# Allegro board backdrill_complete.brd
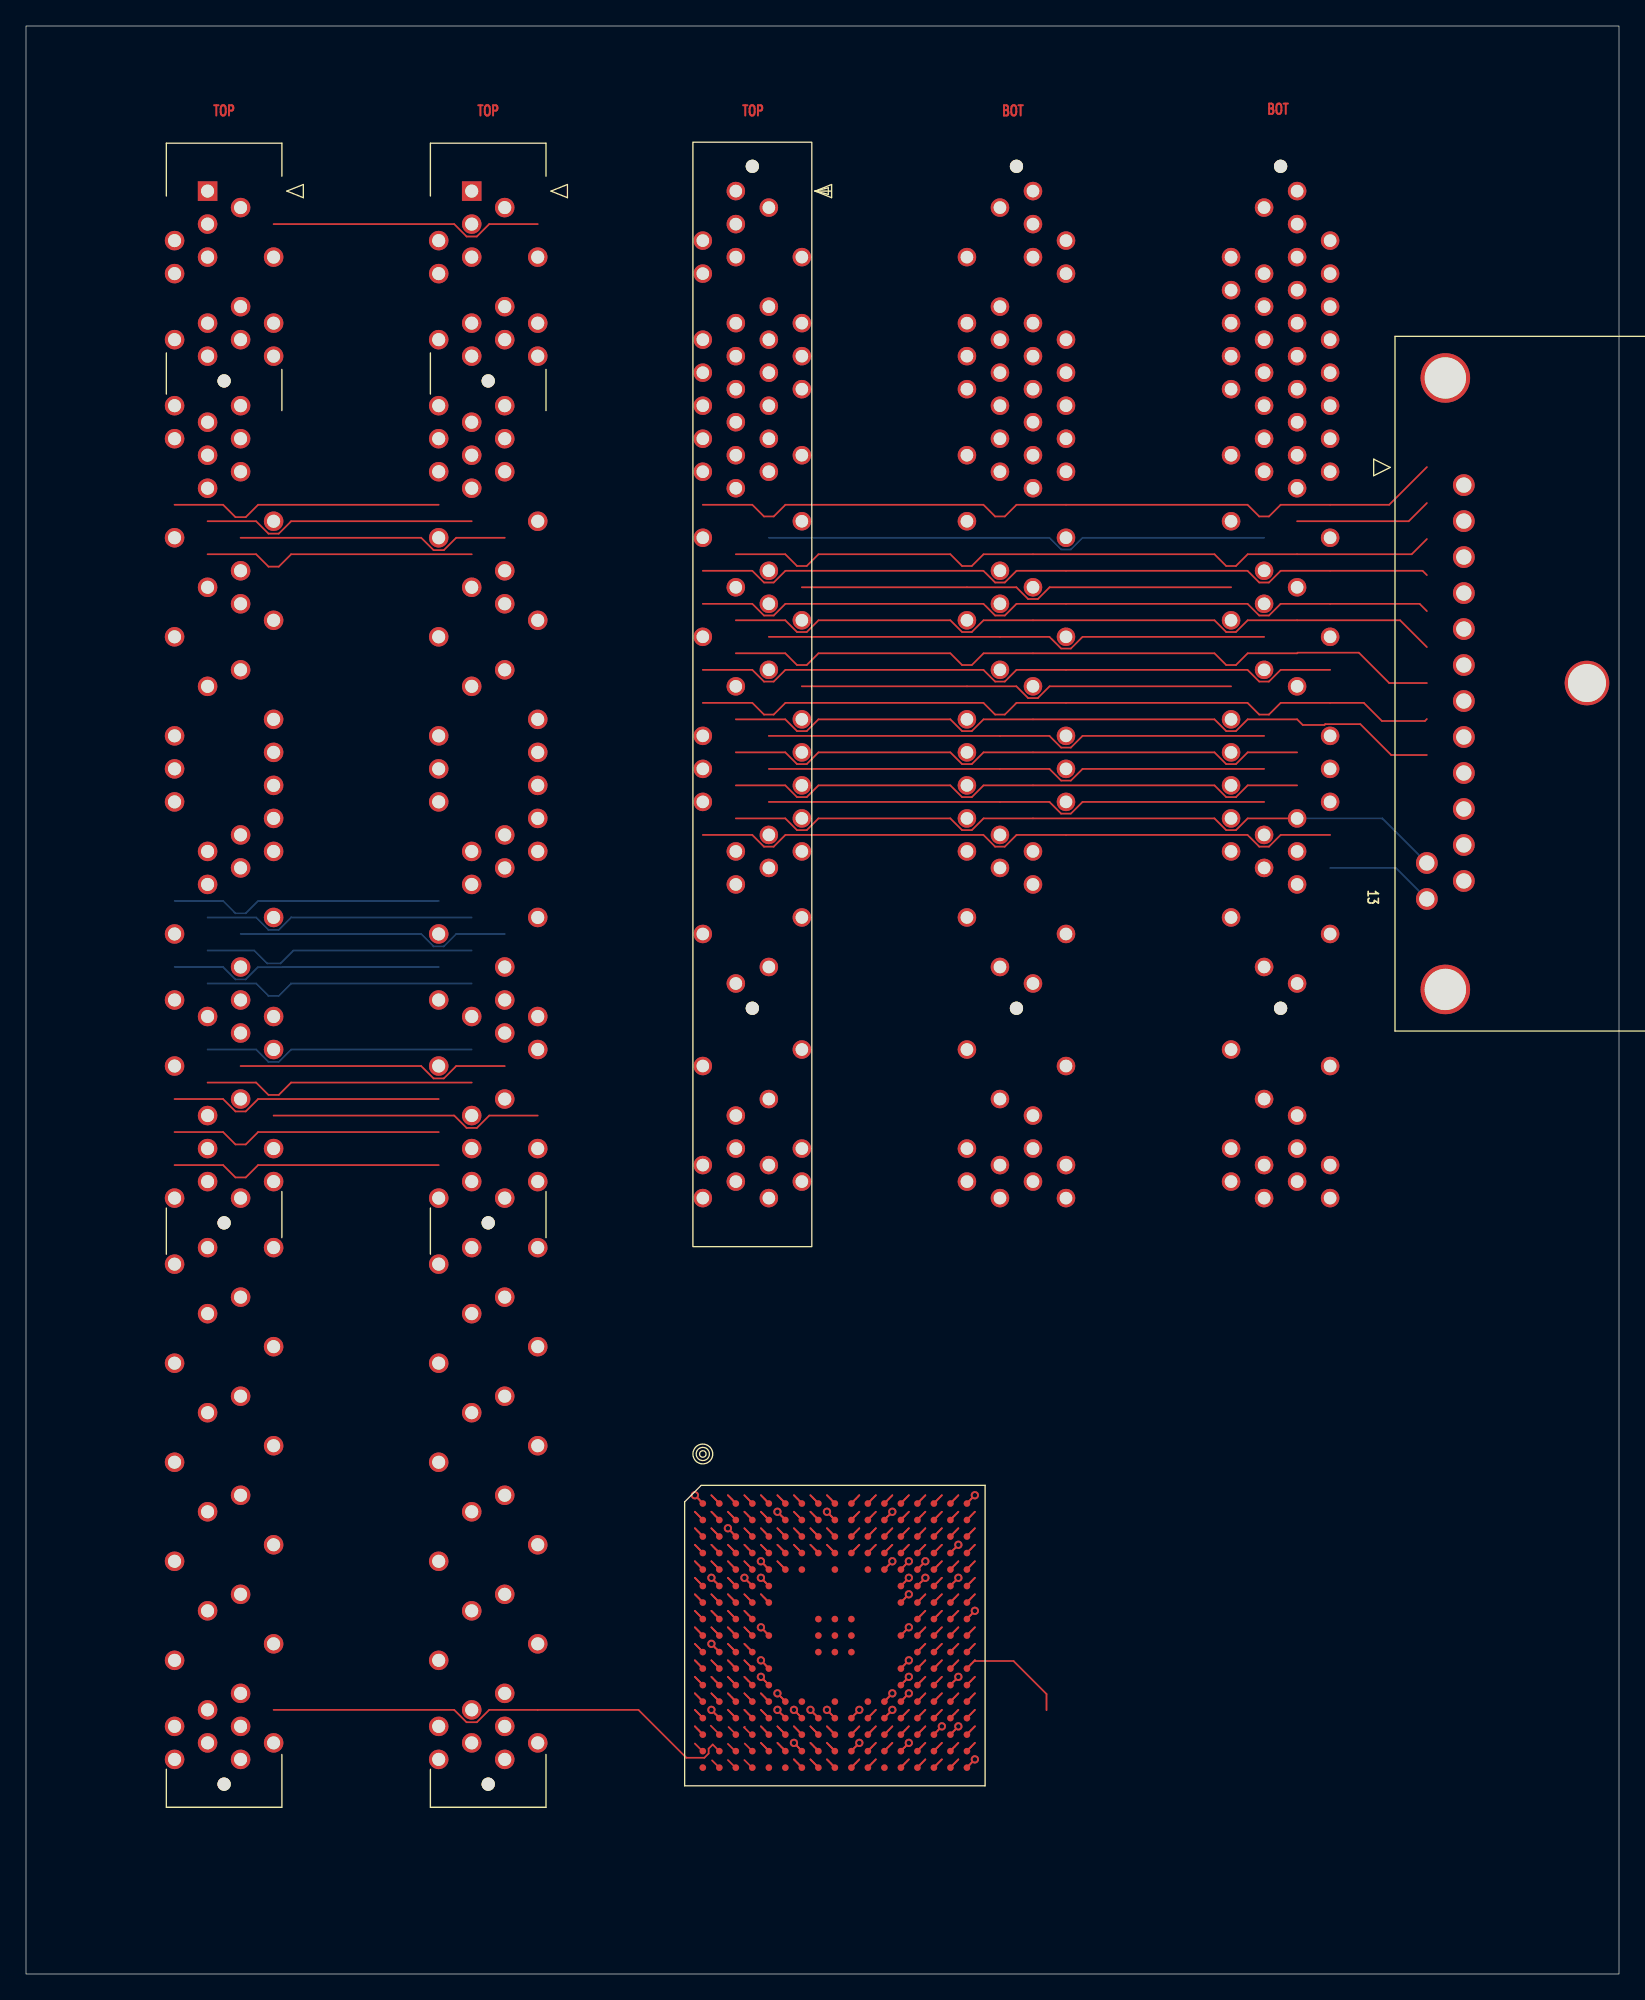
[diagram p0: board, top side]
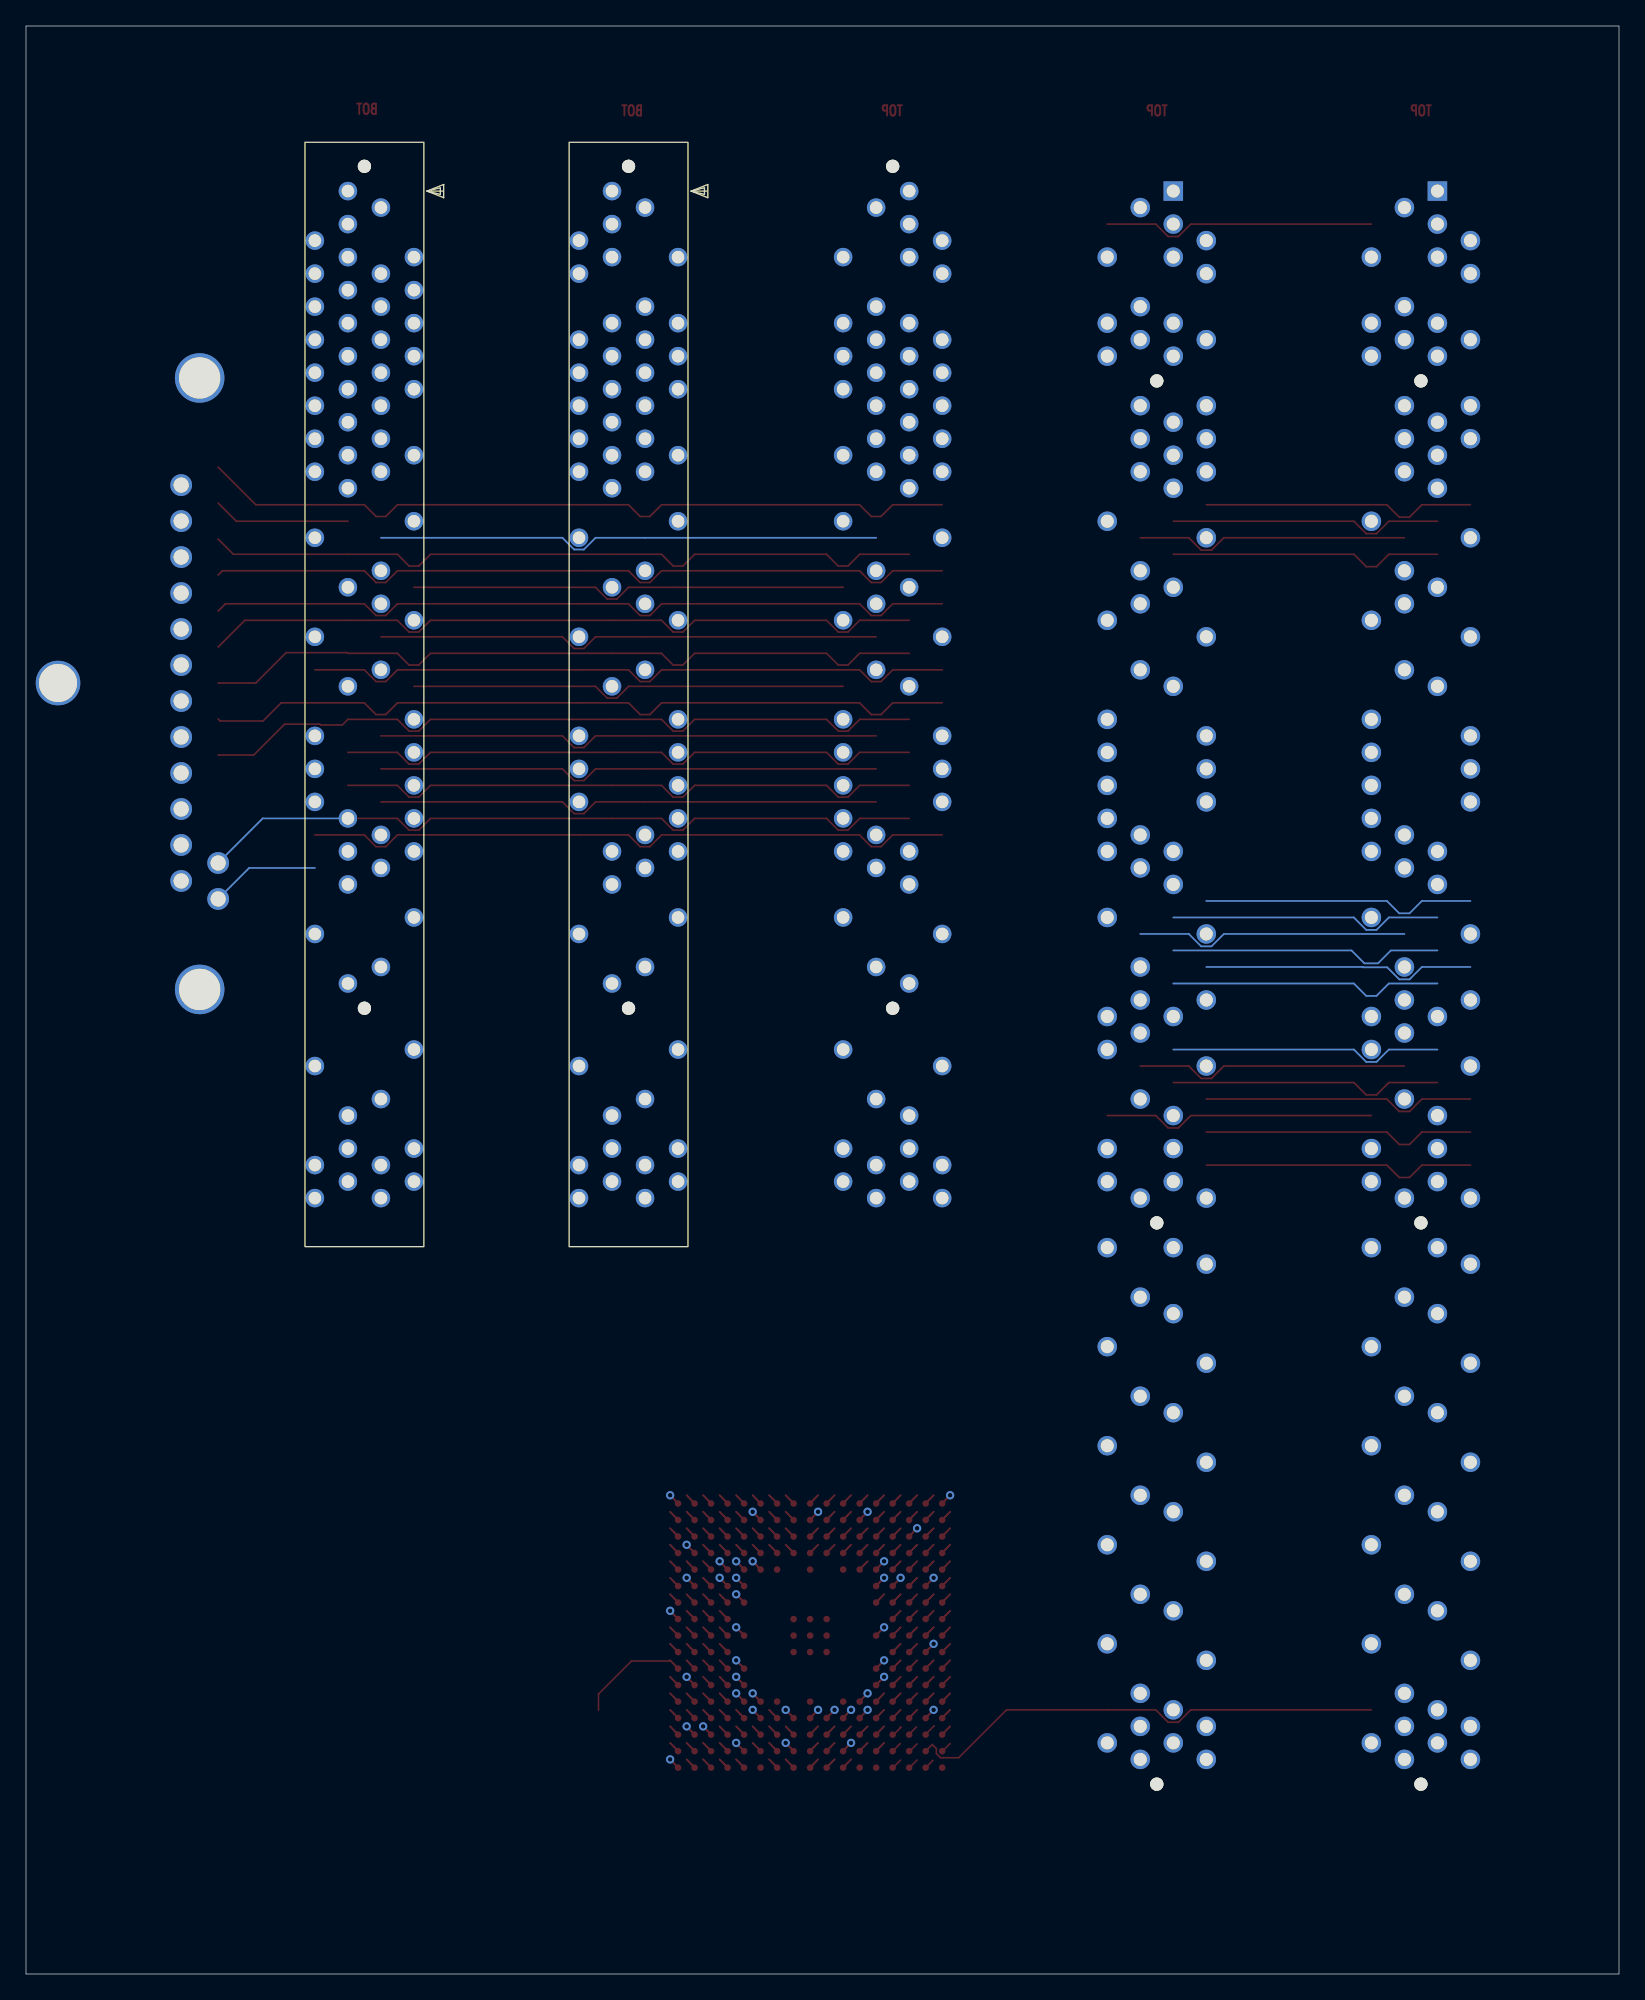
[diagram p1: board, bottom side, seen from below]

Outline 122.56 x 149.86 mm; copper layers: TOP, LAYER_2_P, LAYER_3, LAYER_4_P, LAYER_5, LAYER_6, LAYER_7_P, LAYER_8, LAYER_9_P, BOTTOM. Coordinates in mm from the lower left corner of the outline.
Outline path: 0,149.86 0,0 122.56,0 122.56,149.86 0,149.86

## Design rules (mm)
constraint set DEFAULT: min track width 0.127
net group 6 MIL: nets USB_ICH2_P2+ USB_ICH2_P2-
net group 8 MIL: nets ITP_BCLK0 ITP_BCLK1
net group 92MM_FAN: nets 92MM_FAN TP_FAN_SP_CNTL_10
net group AC_BIT_CLK: nets AC_BIT_CLK AC_BIT_CLK_R
net group AC_SDIN0: nets AC_SDIN0 AC_SDIN0_R
net group AUD_AC97_MIC_C: nets AUD_AC97_MIC_C AUD_MIC_IN
net group AUD_CD_GND: nets AUD_CD_GND AUD_CD_GND_C
net group AUD_L_CD: nets AUD_L_CD AUD_L_CD_C
net group AUD_L_LINE_IN: nets AUD_L_LINE_IN AUD_L_LINE_IN_C
net group AUD_L_LINE_IN_CONN: nets AUD_L_LINE_IN_CONN AUD_L_LINE_IN_CONN_F
net group AUD_MONO_OUT: nets AUD_MONO_OUT AUD_MONO_OUT_C
net group AUD_R_CD: nets AUD_R_CD AUD_R_CD_C
net group AUD_R_LINE_IN: nets AUD_R_LINE_IN AUD_R_LINE_IN_C
net group AUD_R_LINE_IN_CONN: nets AUD_R_LINE_IN_CONN AUD_R_LINE_IN_CONN_F
net group CPU_PROCHOT_L: nets CPU_PROCHOT_L TP_HCTA_PRC_5
net group CPU_THERMTRIP_L: nets SWITCH_CONN_L SWITCH_L
net group CTS1_RS232: nets CTS1_RS232 CTS1_RS232_F
net group DCD1_RS232: nets DCD1_RS232 DCD1_RS232_F
net group DEB_FP_RESET_L: nets DEB_FP_RESET_L FP_RESET_L
net group DIFFPAIR_1: nets USB_ICH2_P3+ USB_ICH2_P3-
net group DRCG_REF_CLKA: nets DRCG_REF_CLKA DRCG_REF_CLKA_R
net group DRCG_REF_CLKB: nets DRCG_REF_CLKB DRCG_REF_CLKB_R
net group DSR1_RS232: nets DSR1_RS232 DSR1_RS232_F
net group DTR1_RS232: nets DTR1_RS232 DTR1_RS232_F
net group FAN_FULL_ON_L: nets FAN_FULL_ON_L TP_FAN_SP_CNTL_16
net group FPACK_N: nets FPACK_N PACK_N
net group FPAUTOFD_N: nets FPAUTOFD_N PAUTOFD_N
net group FPBUSY: nets FPBUSY PBUSY
net group FPDR0: nets FPDR0 PDR0
net group FPDR1: nets FPDR1 PDR1
net group FPDR2: nets FPDR2 PDR2
net group FPDR3: nets FPDR3 PDR3
net group FPDR4: nets FPDR4 PDR4
net group FPDR5: nets FPDR5 PDR5
net group FPDR6: nets FPDR6 PDR6
net group FPDR7: nets FPDR7 PDR7
net group FPERROR: nets FPERROR PERROR
net group FPFAULT_N: nets FPFAULT_N PFAULT_N
net group FPINIT_N: nets FPINIT_N PINITR_N
net group FPSELECT: nets FPSELECT PSELECT
net group FPSLCTIN_N: nets FPSLCTIN_N PSLCTIN_N
net group FWH_33MHZ_CLK: nets FWH_33MHZ_CLK FWH_33MHZ_CLK_R
net group FWH_RST: nets FWH_RST TP_LPC_26
net group GLUE_33MHZ_CLK: nets GLUE_33MHZ_CLK P_33M_GLUE_R
net group HL_B11: nets HL_B11 R_HL_B11
net group HLA_VREF_ICH2: nets HLA_VREF_ICH2 TP_VREF_HLA_ICH2
net group HLB_VREF_P64H: nets HLB_VREF_P64H TP_VREF_HLB_P64H
net group I_SHARE: nets I_SHARE TP_I_SHARE_VRM
net group ICH2_14MHZ_CLK: nets 14M_ICH_SEL1_R ICH2_14MHZ_CLK
net group ICH2_33MHZ_CLK: nets ICH2_33MHZ_CLK P_33M_ICH_R
net group ICH2_66MHZ_CLK: nets HBL_66M_ICH_R ICH2_66MHZ_CLK
net group ICH2_LAN_CLK: nets ICH2_LAN_CLK ICH2_LAN_CLK_JCLK
net group ICH2_LAN_RXD0: nets ICH2_LAN_RXD0 R_ICH2_LAN_RXD0
net group KBCLK_F: nets KBCLK_F KBCLK_R
net group KBDATA_F: nets KBDATA_F KBDATA_R
net group LAN_RDN: nets LAN_RDN LAN_RDP
net group LAN_TDN: nets LAN_TDN LAN_TDP
net group MAIN_VBAT_R: nets MAIN_VBAT_R V_BIAS_C
net group MCH_BCLK0: nets MCH_BCLK0 MCH_BCLK0_R
net group MCH_BCLK1: nets MCH_BCLK1 MCH_BCLK1_R
net group MSECLK_F: nets MSECLK_F MSECLK_R
net group MSEDATA_F: nets MSEDATA_F MSEDATA_R
net group P0_BCLK0: nets P0_BCLK0 P0_BCLK0_R
net group P0_BCLK1: nets P0_BCLK1 P0_BCLK1_R
net group P1_BCLK0: nets P1_BCLK0 P1_BCLK0_R
net group P1_BCLK1: nets P1_BCLK1 P1_BCLK1_R
net group P66_PCIRST_L: nets P66_PCIRST_L TP_P66_PCIRST_L_R
net group PCI0_33MHZ_CLK: nets PCI0_33MHZ_CLK PCI0_33MHZ_CLK_R
net group PCI1_33MHZ_CLK: nets PCI1_33MHZ_CLK PCI1_33MHZ_CLK_R
net group PCI2_33MHZ_CLK: nets PCI2_33MHZ_CLK PCI2_33MHZ_CLK_R
net group RI1_RS232: nets RI1_RS232 RI1_RS232_F
net group RING_N: nets RING_N TP_GD75232_12
net group RTC_XTAL_1: nets RTC_XTAL_1 RTC_XTAL_2
net group RTS1_RS232: nets RTS1_RS232 RTS1_RS232_F
net group SIN1_RS232: nets SIN1_RS232 SIN1_RS232_F
net group SIO_14MHZ_CLK: nets 14M_SIO_SEL0_R SIO_14MHZ_CLK
net group SIO_33MHZ_CLK: nets P_33M_SIOCLK_R SIO_33MHZ_CLK
net group SKTOCC_1_L: nets SKTOCC_1_L TP_BUSPARK
net group SLP_S3_R1: nets SLP_S3_R1 TP_WAKEON_F08_8
net group SLP_S5_L: nets SLP_S5_L TP_FET39_1_5
net group SOUT1_RS232: nets SOUT1_RS232 SOUT1_RS232_F
net group SUSCLK: nets SUSCLK TP_ICH_K4
net group THERMDN: nets THERMDN THERMDP
net group TP_1881_5: nets AC_SDOUT TP_1881_5
net group TP_1881_10: nets AC_SYNC TP_1881_10
net group TP_1881_11: nets AC_RST_L TP_1881_11
net group TP_AD1881_34: nets TP_AD1881_33 TP_AD1881_34
net group TP_AMP1_26: nets AUD_CDC_R_OUT TP_AMP1_26
net group TP_AMP2_23: nets AUD_CDC_L_OUT TP_AMP2_23
net group TP_FAN_SP_CNTL_1: nets FAN_FULL_L TP_FAN_SP_CNTL_1
net group TP_FAN_SP_CNTL_2: nets TP_FAN_SP_CNTL_2 TP_FAN_SP_CNTL_3
net group TP_FAN_SP_CNTL_8: nets TP_FAN_SP_CNTL_8 TP_FAN_SP_CNTL_9
net group TP_FB_1: nets TP_FB_1 TP_FB_8
net group TP_FB_2: nets TP_FB_2 TP_FB_7
net group TP_FWU_CPU_INIT: nets CPU_INIT_L TP_FWU_CPU_INIT
net group TP_HLA_VREF_MCH: nets HLA_VREF_MCH TP_HLA_VREF_MCH
net group TP_MCH_SSI_ST: nets MCH_SSI_ST TP_MCH_SSI_ST
net group TP_Q23_1: nets AUD_NOPOP TP_Q23_1
net group TP_SPARES_45: nets TP_SPARES_45 TP_SPARES_46
net group TP_SPARES_47: nets TP_SPARES_47 TP_SPARES_48
net group TP_SPARES_49: nets TP_SPARES_49 TP_SPARES_50
net group TP_SPARES_51: nets TP_SPARES_51 TP_SPARES_52
net group TP_SPARES_53: nets TP_SPARES_53 TP_SPARES_54
net group TP_SPARES_57: nets TP_SPARES_57 TP_SPARES_58
net group TP_SPARES_59: nets TP_SPARES_59 TP_SPARES_60
net group TP_SPARES_93: nets TP_SPARES_93 TP_SPARES_94
net group TP_SPARES_95: nets TP_SPARES_95 TP_SPARES_96
net group TP_SPARES_97: nets TP_SPARES_97 TP_SPARES_98
net group TP_TESTRS_1: nets TP_TESTRS_1 TP_TESTRS_2
net group TP_TESTRS_3: nets TP_TESTRS_3 TP_TESTRS_4
net group TP_TESTRS_5: nets TP_TESTRS_5 TP_TESTRS_6
net group TP_TESTRS_7: nets TP_TESTRS_7 TP_TESTRS_8
net group TP_TESTRS_10: nets TP_TESTRS_9 TP_TESTRS_10
net group TP_TSTCPS_1: nets TP_TSTCPS_1 TP_TSTCPS_2
net group TP_TSTCPS_3: nets TP_TSTCPS_3 TP_TSTCPS_4
net group TP_TSTCPS_5: nets TP_TSTCPS_5 TP_TSTCPS_6
net group TP_TSTCPS_7: nets TP_TSTCPS_7 TP_TSTCPS_8
net group TP_TSTCPS_10: nets TP_TSTCPS_9 TP_TSTCPS_10
net group TP_TSTCPS_11: nets TP_TSTCPS_11 TP_TSTCPS_12
net group TP_TSTCPS_13: nets TP_TSTCPS_13 TP_TSTCPS_14
net group TP_TSTCPS_15: nets TP_TSTCPS_15 TP_TSTCPS_16
net group TP_TSTCPS_17: nets TP_TSTCPS_17 TP_TSTCPS_18
net group TP_TSTCPS_19: nets TP_TSTCPS_19 TP_TSTCPS_20
net group TP_TSTCPS_21: nets TP_TSTCPS_21 TP_TSTCPS_22
net group TP_TSTCPS_23: nets TP_TSTCPS_23 TP_TSTCPS_24
net group TP_TSTCPS_25: nets TP_TSTCPS_25 TP_TSTCPS_26
net group TP_TSTCPS_27: nets TP_TSTCPS_27 TP_TSTCPS_28
net group TP_TSTCPS_29: nets TP_TSTCPS_29 TP_TSTCPS_30
net group TP_TSTCPS_31: nets TP_TSTCPS_31 TP_TSTCPS_32
net group TP_TSTCPS_33: nets TP_TSTCPS_33 TP_TSTCPS_34
net group TP_TSTCPS_35: nets TP_TSTCPS_35 TP_TSTCPS_36
net group TP_TSTCPS_37: nets TP_TSTCPS_37 TP_TSTCPS_38
net group TP_U7_37: nets SLP_S3_L TP_U7_37
net group TP_VREF1_GTL1_P0: nets GTL_VREF1_P0 TP_VREF1_GTL1_P0
net group TP_VREF2_GTL2_P0: nets GTL_VREF2_P0 TP_VREF2_GTL2_P0
net group TP_VREF3_GTL1_P1: nets GTL_VREF1_P1 TP_VREF3_GTL1_P1
net group TP_VREF3_GTL2_P1: nets GTL_VREF2_P1 TP_VREF3_GTL2_P1
net group TP_VREF5_GTL_1: nets GTL_VREF_MCH TP_VREF5_GTL_1
net group TP_VREF_HUB_MCH: nets HLB_VREF_MCH TP_VREF_HUB_MCH
net group U6_F1: nets RSM_RST_L U6_F1
net group USB_ICH2_OC_L0: nets TP_USB1_FB_1 USB_ICH2_OC_L0
net group USB_ICH2_OC_L1: nets TP_USB2_FB_1 USB_ICH2_OC_L1
net group USB_ICH2_OC_L2: nets TP_USB3_FB_1 USB_ICH2_OC_L2
net group USB_ICH2_P0+: nets USB_ICH2_P0+ USB_P0_F
net group USB_ICH2_P0-: nets USB_ICH2_P0- USB_N0_F
net group USB_ICH2_P1+: nets USB_ICH2_P1+ USB_P1_F
net group USB_ICH2_P1-: nets USB_ICH2_P1- USB_N1_F
net group VID_P00: nets VID_P00 VRM_VID0
net group 10 MIL: nets 80CON_CBL_DET_PRI 80CON_CBL_DET_SEC AGP_66MHZ_CLK CPU_A20M_L CPU_IGNNE_L CPU_LINT0_INTR CPU_LINT1_NMI CPU_SMI_L CPU_THERMTRIP_L ICH2_USB_48MHZ_CLK ICH_SMBCLK IDE_IRQ_14_L IDE_IRQ_15_L IDE_LED1_L IDE_LED2_L IDE_PDA0 IDE_PDA1 IDE_PDA2 IDE_PDCS1_L IDE_PDCS3_L IDE_PDD0 IDE_PDD1 IDE_PDD2 IDE_PDD3 IDE_PDD4 IDE_PDD5 IDE_PDD6 IDE_PDD7 IDE_PDD8 IDE_PDD9 IDE_PDD10 IDE_PDD11 IDE_PDD12 IDE_PDD13 IDE_PDD14 IDE_PDD15 IDE_PDDACK_L IDE_PDDREQ IDE_PDIOR_L IDE_PDIOW_L IDE_PIORDY IDE_SDA0 IDE_SDA1 IDE_SDA2 IDE_SDCS1_L IDE_SDCS3_L IDE_SDD0 IDE_SDD1 IDE_SDD2 IDE_SDD3 IDE_SDD4 IDE_SDD5 IDE_SDD6 IDE_SDD7 IDE_SDD8 IDE_SDD9 IDE_SDD10 IDE_SDD11 IDE_SDD12 IDE_SDD13 IDE_SDD14 IDE_SDD15 IDE_SDDACK_L IDE_SDDREQ IDE_SDIOR_L IDE_SDIOW_L IDE_SIORDY P64H_APICCLK_PD PCI0_66MHZ_CLK PCI1_66MHZ_CLK PCI6_66MHZ_CLK SMBUS_PAR1_CLK SMBUS_PAR2_CLK SMBUS_PAR3_CLK
net group 12 MIL: nets M_HCLKOUT_A M_HCLKOUT_B M_RCLKOUT_A M_RCLKOUT_B
net group 15 MIL: nets AGP_AD0 AGP_AD1 AGP_AD2 AGP_AD3 AGP_AD4 AGP_AD5 AGP_AD6 AGP_AD7 AGP_AD8 AGP_AD9 AGP_AD10 AGP_AD11 AGP_AD12 AGP_AD13 AGP_AD14 AGP_AD15 AGP_AD16 AGP_AD17 AGP_AD18 AGP_AD19 AGP_AD20 AGP_AD21 AGP_AD22 AGP_AD23 AGP_AD24 AGP_AD25 AGP_AD26 AGP_AD27 AGP_AD28 AGP_AD29 AGP_AD30 AGP_AD31 AGP_ADSTB0 AGP_ADSTB0_L AGP_ADSTB1 AGP_ADSTB1_L AGP_C_BE_L0 AGP_C_BE_L1 AGP_C_BE_L2 AGP_C_BE_L3 AGP_DEVSEL_L AGP_FRAME_L AGP_GNT_L AGP_IRDY_L AGP_PAR AGP_PIPE_L AGP_RBF_L AGP_REQ_L AGP_SBA0 AGP_SBA1 AGP_SBA2 AGP_SBA3 AGP_SBA4 AGP_SBA5 AGP_SBA6 AGP_SBA7 AGP_SBSTB AGP_SBSTB_L AGP_SERR_L AGP_ST_0 AGP_ST_1 AGP_ST_2 AGP_STOP_L AGP_TRDY_L AGP_WBF_L CPU0_BR0_L CPU1_BR0_L CPU_A20GATE CPU_BPM_L_2_0 CPU_BPM_L_3_1 CPU_BPM_L_4 CPU_BPM_L_5 CPU_FERR_L CPU_PWR_GD CPU_STPCLK_L FSB_A_L17 FSB_A_L18 FSB_A_L19 FSB_A_L20 FSB_A_L21 FSB_A_L22 FSB_A_L23 FSB_A_L24 FSB_A_L25 FSB_A_L26 FSB_A_L27 FSB_A_L28 FSB_A_L29 FSB_A_L30 FSB_A_L31 FSB_A_L32 FSB_A_L33 FSB_A_L34 FSB_A_L35 FSB_ADS_L FSB_ADSTB_L1 FSB_AP_L0 FSB_BNR_L FSB_BPRI_L FSB_CPURST_L FSB_D_L0 FSB_D_L1 FSB_D_L2 FSB_D_L3 FSB_D_L4 FSB_D_L5 FSB_D_L6 FSB_D_L7 FSB_D_L8 FSB_D_L9 FSB_D_L10 FSB_D_L11 FSB_D_L12 FSB_D_L13 FSB_D_L14 FSB_D_L15 FSB_D_L16 FSB_D_L17 FSB_D_L18 FSB_D_L19 FSB_D_L20 FSB_D_L21 FSB_D_L22 FSB_D_L23 FSB_D_L24 FSB_D_L25 FSB_D_L26 FSB_D_L27 FSB_D_L28 FSB_D_L29 FSB_D_L30 FSB_D_L31 FSB_D_L32 FSB_D_L33 FSB_D_L34 FSB_D_L35 FSB_D_L36 FSB_D_L37 FSB_D_L38 FSB_D_L39 FSB_D_L40 FSB_D_L41 FSB_D_L42 FSB_D_L43 FSB_D_L44 FSB_D_L45 FSB_D_L46 FSB_D_L47 FSB_D_L48 FSB_D_L49 FSB_D_L50 FSB_D_L51 FSB_D_L52 FSB_D_L53 FSB_D_L54 FSB_D_L55 FSB_D_L56 FSB_D_L57 FSB_D_L58 FSB_D_L59 FSB_D_L60 FSB_D_L61 FSB_D_L62 FSB_D_L63 FSB_DBI_L0 FSB_DBI_L1 FSB_DBI_L2 FSB_DBI_L3 FSB_DBSY_L FSB_DEFER_L FSB_DRDY_L FSB_DSTBN_L0 FSB_DSTBN_L1 FSB_DSTBN_L2 FSB_DSTBN_L3 FSB_DSTBP_L0 FSB_DSTBP_L1 FSB_DSTBP_L2 FSB_DSTBP_L3 FSB_HIT_L FSB_HITM_L FSB_LOCK_L FSB_RS_L_0 FSB_RS_L_1 FSB_RS_L_2 FSB_RSP_L FSB_TRDY_L ITP_TMS_P MA_EXDQA2 MA_EXDQA5
net group 20 MIL: nets HL_A0 HL_A1 HL_A2 HL_A3 HL_A4 HL_A5 HL_A6 HL_A7 HL_A8 HL_A9 HL_A10 HL_A11 HL_B0 HL_B1 HL_B2 HL_B3 HL_B4 HL_B5 HL_B6 HL_B7 HL_B8 HL_B9 HL_B10 HL_B12 HL_B13 HL_B14 HL_B15 HL_B16 HL_B17 HL_B18 HL_B19 HLA_STB HLA_STB_L HLB_STB0 HLB_STB0_L HLB_STB1 HLB_STB1_L M_DRCG_A M_DRCG_A_L M_DRCG_B M_DRCG_B_L M_EXCFM_A M_EXCFM_A_L M_EXCFM_B M_EXCFM_B_L M_EXCMD_A M_EXCMD_B M_EXCTM_A M_EXCTM_A_L M_EXCTM_B M_EXCTM_B_L M_EXP0_A M_EXP0_B M_EXP1_A M_EXP1_B M_EXSCK_A M_EXSCK_B M_EXSIO_B MA_EXDQA0 MA_EXDQA1 MA_EXDQA3 MA_EXDQA4 MA_EXDQA6 MA_EXDQA7 MA_EXDQA8 MA_EXDQB0 MA_EXDQB1 MA_EXDQB2 MA_EXDQB3 MA_EXDQB4 MA_EXDQB5 MA_EXDQB6 MA_EXDQB7 MA_EXDQB8 MA_EXREQ0 MA_EXREQ1 MA_EXREQ2 MA_EXREQ3 MA_EXREQ4 MA_EXREQ5 MA_EXREQ6 MA_EXREQ7 MA_RAMREF_TM MB_EXDQA0 MB_EXDQA1 MB_EXDQA2 MB_EXDQA3 MB_EXDQA4 MB_EXDQA5 MB_EXDQA6 MB_EXDQA7 MB_EXDQA8 MB_EXDQB0 MB_EXDQB1 MB_EXDQB2 MB_EXDQB3 MB_EXDQB4 MB_EXDQB5 MB_EXDQB6 MB_EXDQB7 MB_EXDQB8 MB_EXREQ0 MB_EXREQ1 MB_EXREQ2 MB_EXREQ3 MB_EXREQ4 MB_EXREQ5 MB_EXREQ6 MB_EXREQ7 MB_RAMREF_TM PCIRST_OUT_L TDR_MECC_L3 TDR_MECC_L6
net group 21 MIL: nets FSB_A_L3 FSB_A_L4 FSB_A_L5 FSB_A_L6 FSB_A_L7 FSB_A_L8 FSB_A_L9 FSB_A_L10 FSB_A_L11 FSB_A_L12 FSB_A_L13 FSB_A_L14 FSB_A_L15 FSB_A_L16 FSB_ADSTB_L0 FSB_REQ_L0 FSB_REQ_L1 FSB_REQ_L2 FSB_REQ_L3 FSB_REQ_L4
net group AGP_66MHZ_CLK: nets AGP_66MHZ_CLK_R
net group AGP_VREF: nets AGP_VREF TP_VREF_AGP_1 TP_VREF_AGP_7 TP_VREF_AGP_8
net group AUD_L_LINE_OUT: nets AUD_L_LINE_OUT AUD_L_LINE_OUT_F TP_LM4880_2 TP_LM4880_7
net group AUD_MIC_AMP_OUT_R: nets AUD_MIC_AMP_OUT_R AUD_MICFB_IN TP_U27_1
net group AUD_MIC_IN_CONN_AMP: nets AUD_MIC_IN_CONN_AMP AUD_MIC_IN_CONN_PH AUD_MIC_IN_PH
net group AUD_MICAPOS_IN_PD: nets AUD_MIC_IN_21 AUD_MIC_IN_PD AUD_MICAPOS_IN_PD
net group AUD_MONO_IN: nets AUD_MONO_IN TP_1881_13 TP_R4051_1
net group AUD_R_LINE_OUT: nets AUD_R_LINE_OUT AUD_R_LINE_OUT_F TP_LM4880_1 TP_LM4880_6
net group CK00_SELA: nets CK00_SELA
net group DRCG_CTRL: nets DRCG_CTRL TP_U2_23 TP_U2_24 TP_U3_23 TP_U3_24
net group INTRUDER_L: nets INTRUDER_L RTCRST_L V_BAT
net group ISEN1_C: nets ISEN1_C PHASE1_C TP_1_8V_RC TP_HIP6601_2
net group ITP_BCLK0: nets ITP_BCLK0_R
net group ITP_BCLK1: nets ITP_BCLK1_R
net group LAN: nets ICH2_LAN_CS ICH2_LAN_DIN ICH2_LAN_DOUT ICH2_LAN_RSTSYNC ICH2_LAN_RXD1 ICH2_LAN_RXD2 ICH2_LAN_SHCLK ICH2_LAN_TXD0 ICH2_LAN_TXD1 ICH2_LAN_TXD2
net group LAN_CK_X2R: nets LAN_CK_X1 LAN_CK_X2 LAN_CK_X2R
net group M_DRCG_A: nets TP_R60_2 TP_U3_DRCG_A TP_U3_DRCG_A_L
net group M_DRCG_B: nets TP_R56_2 TP_U2_DRCG_B TP_U2_DRCG_B_L
net group MA_RAMREF_TM: nets TP_MCH_VREFA
net group MB_RAMREF_TM: nets TP_MCH_VREFB
net group MCH_66MHZ_CLK: nets MCH_66MHZ_CLK MCH_66MHZ_CLK_R TP_MCH_R98
net group P64H_66MHZ_CLK: nets P64H_66MHZ_CLK P64H_66MHZ_CLK_R PLD_66MHZ_CLK TP_P64H_66MHZ_CLK_TERM TP_PLD_RTOC
net group PCI_64: nets P66_ACK64_L P66_AD0 P66_AD1 P66_AD2 P66_AD3 P66_AD4 P66_AD5 P66_AD6 P66_AD7 P66_AD8 P66_AD9 P66_AD10 P66_AD11 P66_AD12 P66_AD13 P66_AD14 P66_AD15 P66_AD16 P66_AD17 P66_AD18 P66_AD19 P66_AD20 P66_AD21 P66_AD22 P66_AD23 P66_AD24 P66_AD25 P66_AD26 P66_AD27 P66_AD28 P66_AD29 P66_AD30 P66_AD31 P66_AD32 P66_AD33 P66_AD34 P66_AD35 P66_AD36 P66_AD37 P66_AD38 P66_AD39 P66_AD40 P66_AD41 P66_AD42 P66_AD43 P66_AD44 P66_AD45 P66_AD46 P66_AD47 P66_AD48 P66_AD49 P66_AD50 P66_AD51 P66_AD52 P66_AD53 P66_AD54 P66_AD55 P66_AD56 P66_AD57 P66_AD58 P66_AD59 P66_AD60 P66_AD61 P66_AD62 P66_AD63 P66_C_BE_L0 P66_C_BE_L1 P66_C_BE_L2 P66_C_BE_L3 P66_C_BE_L4 P66_C_BE_L5 P66_C_BE_L6 P66_C_BE_L7 P66_DEVSEL_L P66_FRAME_L P66_GNT_L0 P66_GNT_L1 P66_IRDY_L P66_IRQ_L4 P66_IRQ_L5 P66_IRQ_L6 P66_IRQ_L7 P66_IRQ_L8 P66_IRQ_L9 P66_IRQ_L10 P66_IRQ_L11 P66_LOCK_L P66_M66EN P66_PAR P66_PAR64 P66_PERR_L P66_REQ64_L P66_REQ_L0 P66_REQ_L1 P66_SERR_L P66_STOP_L P66_TRDY_L
net group PCIRST_L: nets PCIRST_L TP_GLUE_6 TP_ICH_J5 TP_MCH_AB6 TP_P64HR8
net group TP_1881_12: nets R_SPK SPEAKER TP_1881_12 TP_R4056_1
net group TP_AGP_TREM_1: nets TP_AGP_CR3_4 TP_AGP_TREM_1 TP_AGP_TREM_1000PF
net group TP_HIP6301_6: nets TP_HIP6301_6 TP_HIP6301_7 TP_HIP6301_RC
net group TP_J21_1: nets IDE_RSTDRV_L TP_J21_1 TP_J22_1
net group TP_U7_30: nets PWR_GD_PS SLP_S3_R2 TP_U7_30
net group VCCA_P0: nets VCCA_P0 VCCIOPLL_P0 VSSA_P0
net group VCCA_P1: nets VCCA_P1 VCCIOPLL_P1 VSSA_P1
nets with their own width: min track width 0.127; nets M_EXSIO_A
nets with their own width: min track width 0.254; nets HLA_ZCOMP_FROM_ICH HLB_ZCOM_FROM_P64H HLRCOMP_B HRCOMP0 HRCOMP1 TP_PRCOMP_A TP_PRCOMP_E
nets with their own width: min track width 0.305; nets STANDBY3V
nets with their own width: min track width 0.381; nets +3_3V +12V -12V AGP_VDDQ GND P1_8V P5V P12V_CPU SB1_8V SB2.5V SB5V VCC_CORE

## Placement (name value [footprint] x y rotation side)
J2B1  -  [201082-292]  19.05 137.16 0 top
J2B2  -  [201082-292#2]  39.37 137.16 0 top
J3B1  -  [201082-060]  59.69 137.16 0 top
J3B2  -  [201082-060]  72.39 137.16 180 bottom
J4B1  -  [201082-060#2]  92.71 137.16 180 bottom
J7A2  -  [201591-005]  107.77 115.93 0 top
U3D1  -  [BGA241]  52.07 36.2 0 top

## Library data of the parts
J2B1 = PCI64: part number: PCI64_TH-201082-292; room: PCI66_1
J2B2 = PCI64: part number: PCI64_TH-201082-292; room: PCI66_2
J3B1 = CONPCI: part number: CONPCI_TH-201082-060; room: PCI1
J3B2 = CONPCI: part number: CONPCI_TH-201082-060; room: PCI2
J4B1 = CONPCI: part number: CONPCI_TH-201082-060; room: PCI3
J7A2 = DSUB25TALL: part number: DSUB25TALL_TH-3MT-DSUB; room: PARALLEL
U3D1 = P64H: part number: P64H_BGA-732123-007

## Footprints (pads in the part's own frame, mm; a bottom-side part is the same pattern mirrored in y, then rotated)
201082-060
  round 1.016 hole 2.489 unplated: (-3.81,1.905) (-3.81,-62.865)
  round 1.422 hole 0.965: A2(-2.54,-1.27) A5(0,-5.08) A8(-2.54,-8.89) A9(0,-10.16) A10(-2.54,-11.43) A11(0,-12.7) A12(-2.54,-13.97) A13(0,-15.24) A14(-2.54,-16.51) A16(-2.54,-19.05) A17(0,-20.32) A18(-2.54,-21.59) A21(0,-25.4) A24(-2.54,-29.21) A26(-2.54,-31.75) A27(0,-33.02) A30(-2.54,-36.83) A33(0,-40.64) A35(0,-43.18) A37(0,-45.72) A39(0,-48.26) A40(-2.54,-49.53) A41(0,-50.8) A42(-2.54,-52.07) A45(0,-55.88) A48(-2.54,-59.69) A53(0,-66.04) A56(-2.54,-69.85) A59(0,-73.66) A60(-2.54,-74.93) A61(0,-76.2) A62(-2.54,-77.47) B1(-5.08,0) B3(-5.08,-2.54) B4(-7.62,-3.81) B5(-5.08,-5.08) B6(-7.62,-6.35) B9(-5.08,-10.16) B10(-7.62,-11.43) B11(-5.08,-12.7) B12(-7.62,-13.97) B13(-5.08,-15.24) B14(-7.62,-16.51) B15(-5.08,-17.78) B16(-7.62,-19.05) B17(-5.08,-20.32) B18(-7.62,-21.59) B19(-5.08,-22.86) B22(-7.62,-26.67) B25(-5.08,-30.48) B28(-7.62,-34.29) B31(-5.08,-38.1) B34(-7.62,-41.91) B36(-7.62,-44.45) B38(-7.62,-46.99) B41(-5.08,-50.8) B43(-5.08,-53.34) B46(-7.62,-57.15) B49(-5.08,-60.96) B54(-7.62,-67.31) B57(-5.08,-71.12) B59(-5.08,-73.66) B60(-7.62,-74.93) B61(-5.08,-76.2) B62(-7.62,-77.47)
201082-060#2
  round 1.016 hole 2.489 unplated: (-3.81,-62.865) (-3.81,1.905)
  round 1.422 hole 0.965: A2(-2.54,-1.27) A5(0,-5.08) A6(-2.54,-6.35) A7(0,-7.62) A8(-2.54,-8.89) A9(0,-10.16) A10(-2.54,-11.43) A11(0,-12.7) A12(-2.54,-13.97) A13(0,-15.24) A14(-2.54,-16.51) A16(-2.54,-19.05) A17(0,-20.32) A18(-2.54,-21.59) A21(0,-25.4) A24(-2.54,-29.21) A26(-2.54,-31.75) A27(0,-33.02) A30(-2.54,-36.83) A33(0,-40.64) A35(0,-43.18) A37(0,-45.72) A39(0,-48.26) A40(-2.54,-49.53) A41(0,-50.8) A42(-2.54,-52.07) A45(0,-55.88) A48(-2.54,-59.69) A53(0,-66.04) A56(-2.54,-69.85) A59(0,-73.66) A60(-2.54,-74.93) A61(0,-76.2) A62(-2.54,-77.47) B1(-5.08,0) B3(-5.08,-2.54) B4(-7.62,-3.81) B5(-5.08,-5.08) B6(-7.62,-6.35) B7(-5.08,-7.62) B8(-7.62,-8.89) B9(-5.08,-10.16) B10(-7.62,-11.43) B11(-5.08,-12.7) B12(-7.62,-13.97) B13(-5.08,-15.24) B14(-7.62,-16.51) B15(-5.08,-17.78) B16(-7.62,-19.05) B17(-5.08,-20.32) B18(-7.62,-21.59) B19(-5.08,-22.86) B22(-7.62,-26.67) B25(-5.08,-30.48) B28(-7.62,-34.29) B31(-5.08,-38.1) B34(-7.62,-41.91) B36(-7.62,-44.45) B38(-7.62,-46.99) B39(-5.08,-48.26) B41(-5.08,-50.8) B43(-5.08,-53.34) B46(-7.62,-57.15) B49(-5.08,-60.96) B54(-7.62,-67.31) B57(-5.08,-71.12) B59(-5.08,-73.66) B60(-7.62,-74.93) B61(-5.08,-76.2) B62(-7.62,-77.47)
201082-292
  round 1.016 hole 2.438 unplated: (-3.81,-14.605) (-3.81,-79.375) (-3.81,-122.555)
  round 1.5 hole 1: A2(-2.54,-1.27) A5(0,-5.08) A8(-2.54,-8.89) A9(0,-10.16) A10(-2.54,-11.43) A11(0,-12.7) A14(-2.54,-16.51) A16(-2.54,-19.05) A18(-2.54,-21.59) A21(0,-25.4) A24(-2.54,-29.21) A26(-2.54,-31.75) A27(0,-33.02) A30(-2.54,-36.83) A33(0,-40.64) A35(0,-43.18) A37(0,-45.72) A39(0,-48.26) A40(-2.54,-49.53) A41(0,-50.8) A42(-2.54,-52.07) A45(0,-55.88) A48(-2.54,-59.69) A50(-2.54,-62.23) A51(0,-63.5) A52(-2.54,-64.77) A53(0,-66.04) A56(-2.54,-69.85) A59(0,-73.66) A61(0,-76.2) A62(-2.54,-77.47) A63(0,-81.28) A66(-2.54,-85.09) A69(0,-88.9) A72(-2.54,-92.71) A75(0,-96.52) A78(-2.54,-100.33) A81(0,-104.14) A84(-2.54,-107.95) A87(0,-111.76) A90(-2.54,-115.57) A92(-2.54,-118.11) A93(0,-119.38) A94(-2.54,-120.65) B3(-5.08,-2.54) B4(-7.62,-3.81) B5(-5.08,-5.08) B6(-7.62,-6.35) B9(-5.08,-10.16) B10(-7.62,-11.43) B11(-5.08,-12.7) B14(-7.62,-16.51) B15(-5.08,-17.78) B16(-7.62,-19.05) B17(-5.08,-20.32) B19(-5.08,-22.86) B22(-7.62,-26.67) B25(-5.08,-30.48) B28(-7.62,-34.29) B31(-5.08,-38.1) B34(-7.62,-41.91) B36(-7.62,-44.45) B38(-7.62,-46.99) B41(-5.08,-50.8) B43(-5.08,-53.34) B46(-7.62,-57.15) B50(-7.62,-62.23) B51(-5.08,-63.5) B54(-7.62,-67.31) B57(-5.08,-71.12) B59(-5.08,-73.66) B61(-5.08,-76.2) B62(-7.62,-77.47) B63(-5.08,-81.28) B64(-7.62,-82.55) B67(-5.08,-86.36) B70(-7.62,-90.17) B73(-5.08,-93.98) B76(-7.62,-97.79) B79(-5.08,-101.6) B82(-7.62,-105.41) B85(-5.08,-109.22) B88(-7.62,-113.03) B91(-5.08,-116.84) B92(-7.62,-118.11) B93(-5.08,-119.38) B94(-7.62,-120.65)
  rect 1.5x1.5 hole 1: B1(-5.08,0)
201082-292#2
  round 1.016 hole 2.438 unplated: (-3.81,-14.605) (-3.81,-79.375) (-3.81,-122.555)
  round 1.5 hole 1: A2(-2.54,-1.27) A5(0,-5.08) A8(-2.54,-8.89) A9(0,-10.16) A10(-2.54,-11.43) A11(0,-12.7) A14(-2.54,-16.51) A16(-2.54,-19.05) A18(-2.54,-21.59) A21(0,-25.4) A24(-2.54,-29.21) A26(-2.54,-31.75) A27(0,-33.02) A30(-2.54,-36.83) A33(0,-40.64) A35(0,-43.18) A37(0,-45.72) A39(0,-48.26) A40(-2.54,-49.53) A41(0,-50.8) A42(-2.54,-52.07) A45(0,-55.88) A48(-2.54,-59.69) A50(-2.54,-62.23) A51(0,-63.5) A52(-2.54,-64.77) A53(0,-66.04) A56(-2.54,-69.85) A59(0,-73.66) A61(0,-76.2) A62(-2.54,-77.47) A63(0,-81.28) A66(-2.54,-85.09) A69(0,-88.9) A72(-2.54,-92.71) A75(0,-96.52) A78(-2.54,-100.33) A81(0,-104.14) A84(-2.54,-107.95) A87(0,-111.76) A90(-2.54,-115.57) A92(-2.54,-118.11) A93(0,-119.38) A94(-2.54,-120.65) B3(-5.08,-2.54) B4(-7.62,-3.81) B5(-5.08,-5.08) B6(-7.62,-6.35) B9(-5.08,-10.16) B10(-7.62,-11.43) B11(-5.08,-12.7) B14(-7.62,-16.51) B15(-5.08,-17.78) B16(-7.62,-19.05) B17(-5.08,-20.32) B18(-7.62,-21.59) B19(-5.08,-22.86) B22(-7.62,-26.67) B25(-5.08,-30.48) B28(-7.62,-34.29) B31(-5.08,-38.1) B34(-7.62,-41.91) B36(-7.62,-44.45) B38(-7.62,-46.99) B41(-5.08,-50.8) B43(-5.08,-53.34) B46(-7.62,-57.15) B50(-7.62,-62.23) B51(-5.08,-63.5) B54(-7.62,-67.31) B57(-5.08,-71.12) B59(-5.08,-73.66) B61(-5.08,-76.2) B62(-7.62,-77.47) B63(-5.08,-81.28) B64(-7.62,-82.55) B67(-5.08,-86.36) B70(-7.62,-90.17) B73(-5.08,-93.98) B76(-7.62,-97.79) B79(-5.08,-101.6) B82(-7.62,-105.41) B85(-5.08,-109.22) B88(-7.62,-113.03) B91(-5.08,-116.84) B92(-7.62,-118.11) B93(-5.08,-119.38) B94(-7.62,-120.65)
  rect 1.5x1.5 hole 1: B1(-5.08,0)
201591-005
  round 1.676 hole 1.168: 12(0,-30.455) 13(0,-33.223) 14(2.845,-1.384) 15(2.845,-4.153) 16(2.845,-6.921) 17(2.845,-9.69) 18(2.845,-12.459) 19(2.845,-15.227) 20(2.845,-17.996) 21(2.845,-20.765) 22(2.845,-23.533) 23(2.845,-26.302) 24(2.845,-29.07) 25(2.845,-31.839)
  round 3.81 hole 3.175: 26(1.422,-40.183) 27(1.422,6.858)
  round 3.429 hole 2.921: 28(12.319,-16.612)
BGA241
  round 0.508 smd: A1(0,0) A2(1.27,0) A3(2.54,0) A4(3.81,0) A5(5.08,0) A6(6.35,0) A7(7.62,0) A8(8.89,0) A9(10.16,0) A10(11.43,0) A11(12.7,0) A12(13.97,0) A13(15.24,0) A14(16.51,0) A15(17.78,0) A16(19.05,0) A17(20.32,0) B1(0,-1.27) B2(1.27,-1.27) B3(2.54,-1.27) B4(3.81,-1.27) B5(5.08,-1.27) B6(6.35,-1.27) B7(7.62,-1.27) B8(8.89,-1.27) B9(10.16,-1.27) B10(11.43,-1.27) B11(12.7,-1.27) B12(13.97,-1.27) B13(15.24,-1.27) B14(16.51,-1.27) B15(17.78,-1.27) B16(19.05,-1.27) B17(20.32,-1.27) C1(0,-2.54) C2(1.27,-2.54) C3(2.54,-2.54) C4(3.81,-2.54) C5(5.08,-2.54) C6(6.35,-2.54) C7(7.62,-2.54) C8(8.89,-2.54) C9(10.16,-2.54) C10(11.43,-2.54) C11(12.7,-2.54) C12(13.97,-2.54) C13(15.24,-2.54) C14(16.51,-2.54) C15(17.78,-2.54) C16(19.05,-2.54) C17(20.32,-2.54) D1(0,-3.81) D2(1.27,-3.81) D3(2.54,-3.81) D4(3.81,-3.81) D5(5.08,-3.81) D6(6.35,-3.81) D7(7.62,-3.81) D8(8.89,-3.81) D9(10.16,-3.81) D10(11.43,-3.81) D11(12.7,-3.81) D12(13.97,-3.81) D13(15.24,-3.81) D14(16.51,-3.81) D15(17.78,-3.81) D16(19.05,-3.81) D17(20.32,-3.81) E1(0,-5.08) E2(1.27,-5.08) E3(2.54,-5.08) E4(3.81,-5.08) E5(5.08,-5.08) E6(6.35,-5.08) E7(7.62,-5.08) E9(10.16,-5.08) E11(12.7,-5.08) E12(13.97,-5.08) E13(15.24,-5.08) E14(16.51,-5.08) E15(17.78,-5.08) E16(19.05,-5.08) E17(20.32,-5.08) F1(0,-6.35) F2(1.27,-6.35) F3(2.54,-6.35) F4(3.81,-6.35) F5(5.08,-6.35) F13(15.24,-6.35) F14(16.51,-6.35) F15(17.78,-6.35) F16(19.05,-6.35) F17(20.32,-6.35) G1(0,-7.62) G2(1.27,-7.62) G3(2.54,-7.62) G4(3.81,-7.62) G5(5.08,-7.62) G13(15.24,-7.62) G14(16.51,-7.62) G15(17.78,-7.62) G16(19.05,-7.62) G17(20.32,-7.62) H1(0,-8.89) H2(1.27,-8.89) H3(2.54,-8.89) H4(3.81,-8.89) H8(8.89,-8.89) H9(10.16,-8.89) H10(11.43,-8.89) H14(16.51,-8.89) H15(17.78,-8.89) H16(19.05,-8.89) H17(20.32,-8.89) J1(0,-10.16) J2(1.27,-10.16) J3(2.54,-10.16) J4(3.81,-10.16) J5(5.08,-10.16) J8(8.89,-10.16) J9(10.16,-10.16) J10(11.43,-10.16) J13(15.24,-10.16) J14(16.51,-10.16) J15(17.78,-10.16) J16(19.05,-10.16) J17(20.32,-10.16) K1(0,-11.43) K2(1.27,-11.43) K3(2.54,-11.43) K4(3.81,-11.43) K8(8.89,-11.43) K9(10.16,-11.43) K10(11.43,-11.43) K14(16.51,-11.43) K15(17.78,-11.43) K16(19.05,-11.43) K17(20.32,-11.43) L1(0,-12.7) L2(1.27,-12.7) L3(2.54,-12.7) L4(3.81,-12.7) L5(5.08,-12.7) L13(15.24,-12.7) L14(16.51,-12.7) L15(17.78,-12.7) L16(19.05,-12.7) L17(20.32,-12.7) M1(0,-13.97) M2(1.27,-13.97) M3(2.54,-13.97) M4(3.81,-13.97) M5(5.08,-13.97) M13(15.24,-13.97) M14(16.51,-13.97) M15(17.78,-13.97) M16(19.05,-13.97) M17(20.32,-13.97) N1(0,-15.24) N2(1.27,-15.24) N3(2.54,-15.24) N4(3.81,-15.24) N5(5.08,-15.24) N6(6.35,-15.24) N7(7.62,-15.24) N9(10.16,-15.24) N11(12.7,-15.24) N12(13.97,-15.24) N13(15.24,-15.24) N14(16.51,-15.24) N15(17.78,-15.24) N16(19.05,-15.24) N17(20.32,-15.24) P1(0,-16.51) P2(1.27,-16.51) P3(2.54,-16.51) P4(3.81,-16.51) P5(5.08,-16.51) P6(6.35,-16.51) P7(7.62,-16.51) P8(8.89,-16.51) P9(10.16,-16.51) P10(11.43,-16.51) P11(12.7,-16.51) P12(13.97,-16.51) P13(15.24,-16.51) P14(16.51,-16.51) P15(17.78,-16.51) P16(19.05,-16.51) P17(20.32,-16.51) R1(0,-17.78) R2(1.27,-17.78) R3(2.54,-17.78) R4(3.81,-17.78) R5(5.08,-17.78) R6(6.35,-17.78) R7(7.62,-17.78) R8(8.89,-17.78) R9(10.16,-17.78) R10(11.43,-17.78) R11(12.7,-17.78) R12(13.97,-17.78) R13(15.24,-17.78) R14(16.51,-17.78) R15(17.78,-17.78) R16(19.05,-17.78) R17(20.32,-17.78) T1(0,-19.05) T2(1.27,-19.05) T3(2.54,-19.05) T4(3.81,-19.05) T5(5.08,-19.05) T6(6.35,-19.05) T7(7.62,-19.05) T8(8.89,-19.05) T9(10.16,-19.05) T10(11.43,-19.05) T11(12.7,-19.05) T12(13.97,-19.05) T13(15.24,-19.05) T14(16.51,-19.05) T15(17.78,-19.05) T16(19.05,-19.05) T17(20.32,-19.05) U1(0,-20.32) U2(1.27,-20.32) U3(2.54,-20.32) U4(3.81,-20.32) U5(5.08,-20.32) U6(6.35,-20.32) U7(7.62,-20.32) U8(8.89,-20.32) U9(10.16,-20.32) U10(11.43,-20.32) U11(12.7,-20.32) U12(13.97,-20.32) U13(15.24,-20.32) U14(16.51,-20.32) U15(17.78,-20.32) U16(19.05,-20.32) U17(20.32,-20.32)

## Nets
+12V: J2B1.A2 J2B2.A2 J3B1.A2 J3B2.A2 J4B1.A2
-12V: J2B1.B1 J2B2.B1 J3B1.B1 J3B2.B1 J4B1.B1
AGND: J7A2.18 J7A2.19 J7A2.20 J7A2.21 J7A2.22 J7A2.23 J7A2.24 J7A2.25 J7A2.26 J7A2.27 J7A2.28
GND: J2B1.A18 J2B1.A24 J2B1.A30 J2B1.A35 J2B1.A37 J2B1.A42 J2B1.A48 J2B1.A50 J2B1.A51 J2B1.A56 J2B1.A63 J2B1.A69 J2B1.A72 J2B1.A78 J2B1.A81 J2B1.A87 J2B1.A90 J2B1.A93 J2B1.B3 J2B1.B15 J2B1.B17 J2B1.B22 J2B1.B28 J2B1.B34 J2B1.B38 J2B1.B46 J2B1.B50 J2B1.B51 J2B1.B57 J2B1.B64 J2B1.B67 J2B1.B73 J2B1.B76 J2B1.B82 J2B1.B85 J2B1.B91 J2B1.B94 J2B2.A18 J2B2.A24 J2B2.A30 J2B2.A35 J2B2.A37 J2B2.A42 J2B2.A48 J2B2.A50 J2B2.A51 J2B2.A56 J2B2.A63 J2B2.A69 J2B2.A72 J2B2.A78 J2B2.A81 J2B2.A87 J2B2.A90 J2B2.A93 J2B2.B3 J2B2.B15 J2B2.B17 J2B2.B22 J2B2.B28 J2B2.B34 J2B2.B38 J2B2.B46 J2B2.B50 J2B2.B51 J2B2.B57 J2B2.B64 J2B2.B67 J2B2.B73 J2B2.B76 J2B2.B82 J2B2.B85 J2B2.B91 J2B2.B94 J3B1.A12 J3B1.A13 J3B1.A18 J3B1.A24 J3B1.A30 J3B1.A35 J3B1.A37 J3B1.A42 J3B1.A48 J3B1.A56 J3B1.B3 J3B1.B12 J3B1.B13 J3B1.B15 J3B1.B17 J3B1.B22 J3B1.B28 J3B1.B34 J3B1.B38 J3B1.B46 J3B1.B49 J3B1.B57 J3B2.A12 J3B2.A13 J3B2.A18 J3B2.A24 J3B2.A30 J3B2.A35 J3B2.A37 J3B2.A42 J3B2.A48 J3B2.A56 J3B2.B3 J3B2.B12 J3B2.B13 J3B2.B15 J3B2.B17 J3B2.B22 J3B2.B28 J3B2.B34 J3B2.B38 J3B2.B46 J3B2.B49 J3B2.B57 J4B1.A12 J4B1.A13 J4B1.A18 J4B1.A24 J4B1.A30 J4B1.A35 J4B1.A37 J4B1.A42 J4B1.A48 J4B1.A56 J4B1.B3 J4B1.B12 J4B1.B13 J4B1.B15 J4B1.B17 J4B1.B22 J4B1.B28 J4B1.B34 J4B1.B38 J4B1.B46 J4B1.B49 J4B1.B57 U3D1.A1 U3D1.A17 U3D1.B6 U3D1.B9 U3D1.B12 U3D1.C3 U3D1.D16 U3D1.E12 U3D1.E14(VSS<9>) U3D1.F2 U3D1.F5 U3D1.F13 U3D1.F16 U3D1.G13 U3D1.H8 U3D1.H9 U3D1.H10 U3D1.J8 U3D1.J9 U3D1.J10 U3D1.K2 U3D1.K8 U3D1.K9 U3D1.K10 U3D1.L5 U3D1.M16 U3D1.N13 U3D1.P2 U3D1.P6 U3D1.P9 U3D1.P12 U3D1.R15 U3D1.R16 U3D1.T7 U3D1.T10 U3D1.T13 U3D1.U1 U3D1.U17
P5V: J2B1.A5 J2B1.A8 J2B1.A61 J2B1.A62 J2B1.B5 J2B1.B6 J2B1.B61 J2B1.B62 J2B2.A5 J2B2.A8 J2B2.A61 J2B2.A62 J2B2.B5 J2B2.B6 J2B2.B61 J2B2.B62 J3B1.A5 J3B1.A8 J3B1.A10 J3B1.A16 J3B1.A59 J3B1.A61 J3B1.A62 J3B1.B5 J3B1.B6 J3B1.B19 J3B1.B59 J3B1.B61 J3B1.B62 J3B2.A5 J3B2.A8 J3B2.A10 J3B2.A16 J3B2.A59 J3B2.A61 J3B2.A62 J3B2.B5 J3B2.B6 J3B2.B19 J3B2.B59 J3B2.B61 J3B2.B62 J4B1.A5 J4B1.A8 J4B1.A10 J4B1.A16 J4B1.A59 J4B1.A61 J4B1.A62 J4B1.B5 J4B1.B6 J4B1.B19 J4B1.B59 J4B1.B61 J4B1.B62
+3_3V: J2B1.A10 J2B1.A16 J2B1.A21 J2B1.A27 J2B1.A33 J2B1.A39 J2B1.A45 J2B1.A53 J2B1.A59 J2B1.A66 J2B1.A75 J2B1.A84 J2B1.B19 J2B1.B25 J2B1.B31 J2B1.B36 J2B1.B41 J2B1.B43 J2B1.B54 J2B1.B59 J2B1.B70 J2B1.B79 J2B1.B88 J2B2.A10 J2B2.A16 J2B2.A21 J2B2.A27 J2B2.A33 J2B2.A39 J2B2.A45 J2B2.A53 J2B2.A59 J2B2.A66 J2B2.A75 J2B2.A84 J2B2.B19 J2B2.B25 J2B2.B31 J2B2.B36 J2B2.B41 J2B2.B43 J2B2.B54 J2B2.B59 J2B2.B70 J2B2.B79 J2B2.B88 J3B1.A21 J3B1.A27 J3B1.A33 J3B1.A39 J3B1.A45 J3B1.A53 J3B1.B25 J3B1.B31 J3B1.B36 J3B1.B41 J3B1.B43 J3B1.B54 J3B2.A21 J3B2.A27 J3B2.A33 J3B2.A39 J3B2.A45 J3B2.A53 J3B2.B25 J3B2.B31 J3B2.B36 J3B2.B41 J3B2.B43 J3B2.B54 J4B1.A21 J4B1.A27 J4B1.A33 J4B1.A39 J4B1.A45 J4B1.A53 J4B1.B25 J4B1.B31 J4B1.B36 J4B1.B41 J4B1.B43 J4B1.B54 U3D1.E5 U3D1.E7 U3D1.E9 U3D1.E11 U3D1.E13 U3D1.F4 U3D1.F14 U3D1.H17 U3D1.J5 U3D1.J13 U3D1.L13 U3D1.M5 U3D1.M13 U3D1.N6 U3D1.N12 U3D1.P7
ACK64_L1: J3B1.B60
ACK64_L2: J3B2.B60
ACK64_L3: J4B1.B60
FPAUTOFD_N: J7A2.14
FPFAULT_N: J7A2.15
FPINIT_N: J7A2.16
FPSLCTIN_N: J7A2.17
GNT_L0: J3B1.A17
GNT_L1: J3B2.A17
GNT_L2: J4B1.A17
HL_B0: U3D1.T8
HL_B1: U3D1.U8
HL_B2: U3D1.R9
HL_B3: U3D1.T9
HL_B4: U3D1.U10
HL_B5: U3D1.P11
HL_B6: U3D1.R11
HL_B7: U3D1.T11
HL_B8: U3D1.P13
HL_B9: U3D1.R13
HL_B10: U3D1.U13
HL_B12: U3D1.U14
HL_B13: U3D1.T15
HL_B14: U3D1.U15
HL_B15: U3D1.U16
HL_B16: U3D1.U12
HL_B17: U3D1.R12
HL_B18: U3D1.U11
HL_B19: U3D1.T12
HLB_STB0: U3D1.R10
HLB_STB0_L: U3D1.U9
HLB_STB1: U3D1.T14
HLB_STB1_L: U3D1.R14
HLB_VREF_P64H: U3D1.T16
HLB_ZCOM_FROM_P64H: U3D1.T17
P1_8V: U3D1.N7 U3D1.N9 U3D1.N11 U3D1.P8 U3D1.P10
P64H_66MHZ_CLK: U3D1.R17
P64H_APICCLK_PD: U3D1.K17
P64H_APICD0_PD: U3D1.G16
P64H_APICD1_PD: U3D1.G15
P66_ACK64_L: U3D1.F1
P66_AD0: U3D1.D1
P66_AD1: U3D1.C1
P66_AD2: U3D1.B1
P66_AD3: U3D1.D2
P66_AD4: U3D1.E2
P66_AD5: U3D1.C2
P66_AD6: U3D1.B2
P66_AD7: U3D1.A2
P66_AD8: U3D1.E3
P66_AD9: U3D1.B3
P66_AD10: U3D1.D4
P66_AD11: U3D1.E4
P66_AD12: U3D1.C4
P66_AD13: U3D1.B4
P66_AD14: U3D1.A4
P66_AD15: U3D1.B5
P66_AD16: U3D1.D9
P66_AD17: U3D1.C9
P66_AD18: U3D1.A9
P66_AD19: U3D1.D10
P66_AD20: U3D1.C10
P66_AD21: U3D1.B10
P66_AD22: U3D1.A10
P66_AD23: U3D1.D11
P66_AD24: U3D1.B11
P66_AD25: U3D1.A11
P66_AD26: U3D1.D12
P66_AD27: U3D1.C12
P66_AD28: U3D1.A12
P66_AD29: U3D1.C13
P66_AD30: U3D1.B13
P66_AD31: U3D1.A13
P66_AD32: U3D1.T2
P66_AD33: U3D1.T1
P66_AD34: U3D1.R4
P66_AD35: U3D1.R3
P66_AD36: U3D1.R2
P66_AD37: U3D1.R1
P66_AD38: U3D1.P4
P66_AD39: U3D1.P3
P66_AD40: U3D1.P1
P66_AD41: U3D1.N4
P66_AD42: U3D1.N3
P66_AD43: U3D1.N2
P66_AD44: U3D1.N1
P66_AD45: U3D1.M4
P66_AD46: U3D1.M3
P66_AD47: U3D1.M2
P66_AD48: U3D1.M1
P66_AD49: U3D1.L4
P66_AD50: U3D1.L3
P66_AD51: U3D1.L2
P66_AD52: U3D1.L1
P66_AD53: U3D1.K4
P66_AD54: U3D1.K3
P66_AD55: U3D1.K1
P66_AD56: U3D1.J4
P66_AD57: U3D1.J3
P66_AD58: U3D1.J2
P66_AD59: U3D1.J1
P66_AD60: U3D1.H4
P66_AD61: U3D1.H3
P66_AD62: U3D1.H2
P66_AD63: U3D1.H1
P66_C_BE_L0: J2B1.A52 J2B2.A52 U3D1.D3
P66_C_BE_L1: U3D1.A5
P66_C_BE_L2: U3D1.A8
P66_C_BE_L3: U3D1.C11
P66_C_BE_L4: U3D1.G5
P66_C_BE_L5: U3D1.G3
P66_C_BE_L6: U3D1.G2
P66_C_BE_L7: U3D1.G1
P66_DEVSEL_L: U3D1.A7
P66_FRAME_L: U3D1.B8
P66_GNT_L0: U3D1.B17
P66_GNT_L1: U3D1.C16
P66_IRDY_L: U3D1.C8
P66_IRQ_L0: U3D1.P17
P66_IRQ_L1: U3D1.P16
P66_IRQ_L2: U3D1.P15
P66_IRQ_L3: U3D1.N17
P66_IRQ_L4: U3D1.N16
P66_IRQ_L5: U3D1.N15
P66_IRQ_L6: U3D1.N14
P66_IRQ_L7: U3D1.M17
P66_IRQ_L8: U3D1.M15
P66_IRQ_L9: U3D1.M14
P66_IRQ_L10: U3D1.L17
P66_IRQ_L11: U3D1.L16
P66_IRQ_L12: U3D1.L15
P66_IRQ_L13: U3D1.L14
P66_IRQ_L14: U3D1.K16
P66_IRQ_L15: U3D1.K15
P66_IRQ_L16: U3D1.K14
P66_IRQ_L17: U3D1.J17
P66_IRQ_L18: U3D1.J15
P66_IRQ_L19: U3D1.J14
P66_IRQ_L20: U3D1.H16
P66_IRQ_L21: U3D1.H15
P66_IRQ_L22: U3D1.H14
P66_IRQ_L23: U3D1.G17
P66_LOCK_L: U3D1.C7
P66_M66EN: U3D1.A3
P66_PAR: U3D1.D6
P66_PAR64: U3D1.G4
P66_PERR_L: U3D1.D7
P66_PRSNT1_1: J2B1.B9
P66_PRSNT1_2: J2B1.B11
P66_PRSNT2_1: J2B2.B9
P66_PRSNT2_2: J2B2.B11
P66_REQ64_L: U3D1.F3
P66_REQ_L0: U3D1.A15
P66_REQ_L1: J2B2.B18 U3D1.D14
P66_REQ_L2: U3D1.C14
P66_REQ_L3: U3D1.B14
P66_REQ_L4: U3D1.A14
P66_REQ_L5: U3D1.D13
P66_SERR_L: U3D1.C6
P66_STOP_L: U3D1.B7
P66_TRDY_L: U3D1.D8
PCI0_33MHZ_CLK: J3B1.B16
PCI0_66MHZ_CLK: J2B1.B16
PCI1_33MHZ_CLK: J3B2.B16
PCI1_66MHZ_CLK: J2B2.B16
PCI2_33MHZ_CLK: J4B1.B16
PCI6_66MHZ_CLK: U3D1.E1
PIRQ_E_L: J4B1.B7 U3D1.G14
PIRQ_F_L: J4B1.A6
PIRQ_G_L: J4B1.A7
PIRQ_H_L: J4B1.B8
PLOCK_L: J4B1.B39 J7A2.12
PRSNT1_1_L: J3B1.B9
PRSNT1_2_L: J3B2.B9
PRSNT1_3_L: J4B1.B9
PRSNT2_1_L: J3B1.B11
PRSNT2_2_L: J3B2.B11
PRSNT2_3_L: J4B1.B11
PWR_GD_3_3: U3D1.U6
R_HL_B11: U3D1.P14
REQ64_L1: J3B1.A60
REQ64_L2: J3B2.A60
REQ64_L3: J4B1.A60
REQ_L0: J3B1.B18
REQ_L1: J3B2.B18
REQ_L2: J4B1.B18
SERR_L: J7A2.13
STANDBY3V: J2B1.A14 J2B2.A14 J3B1.A14 J3B2.A14 J4B1.A14
TP_HP_INTR_L: U3D1.U7
TP_HP_SIC: U3D1.U2
TP_HP_SILB: U3D1.T3
TP_HP_SOC: U3D1.N5
TP_HP_SOD: U3D1.T5
TP_HP_SOL: U3D1.P5
TP_HP_SOLR: U3D1.R5
TP_HP_SORB: U3D1.T4
TP_HP_SORRB: U3D1.U4
TP_P64H_A6: U3D1.A6
TP_P64H_A16: U3D1.A16
TP_P64H_B15: U3D1.B15
TP_P64H_B16: U3D1.B16
TP_P64H_C5: U3D1.C5
TP_P64H_C15: U3D1.C15
TP_P64H_D5: U3D1.D5
TP_P64H_D15: U3D1.D15
TP_P64H_D17: U3D1.D17
TP_P64H_E6: U3D1.E6
TP_P64H_E15: U3D1.E15
TP_P64H_E16: U3D1.E16
TP_P64H_E17: U3D1.E17
TP_P64H_F15: U3D1.F15
TP_P64H_F17: U3D1.F17
TP_P64H_R6: U3D1.R6
TP_P64H_R7: U3D1.R7
TP_P64H_T6: U3D1.T6
TP_P64H_TEST: U3D1.J16
TP_P64H_U3: U3D1.U3
TP_P64H_U5: U3D1.U5
TP_P64HR8: U3D1.R8
TP_P66_PCIRST_L_R: U3D1.C17
TP_P66_TDO_SLOT1: J2B1.B4
TP_P66_TDO_SLOT2: J2B2.B4
TP_PCI1_A9: J3B1.A9
TP_PCI1_A11: J3B1.A11
TP_PCI1_A26: J3B1.A26
TP_PCI1_A40: J3B1.A40
TP_PCI1_A41: J3B1.A41
TP_PCI1_B4: J3B1.B4
TP_PCI1_B10: J3B1.B10
TP_PCI1_B14: J3B1.B14
TP_PCI2_A9: J3B2.A9
TP_PCI2_A11: J3B2.A11
TP_PCI2_A26: J3B2.A26
TP_PCI2_B4: J3B2.B4
TP_PCI2_B10: J3B2.B10
TP_PCI2_B14: J3B2.B14
TP_PCI3_A9: J4B1.A9
TP_PCI3_A11: J4B1.A11
TP_PCI3_A26: J4B1.A26
TP_PCI3_A40: J4B1.A40
TP_PCI3_A41: J4B1.A41
TP_PCI3_B4: J4B1.B4
TP_PCI3_B10: J4B1.B10
TP_PCI3_B14: J4B1.B14
TP_PCI64_A40_SLOT1: J2B1.A40
TP_PCI64_A40_SLOT2: J2B2.A40
TP_PCI64_A41_SLOT1: J2B1.A41
TP_PCI64_A41_SLOT2: J2B2.A41
TP_PCI642_A9: J2B1.A9
TP_PCI642_A11: J2B1.A11
TP_PCI642_A26: J2B1.A26
TP_PCI642_A92: J2B1.A92
TP_PCI642_A94: J2B1.A94(RESERVED8)
TP_PCI642_B10: J2B1.B10
TP_PCI642_B14: J2B1.B14
TP_PCI642_B63: J2B1.B63
TP_PCI642_B92: J2B1.B92
TP_PCI642_B93: J2B1.B93
TP_PCI643_A9: J2B2.A9
TP_PCI643_A11: J2B2.A11
TP_PCI643_A26: J2B2.A26
TP_PCI643_A92: J2B2.A92
TP_PCI643_A94: J2B2.A94(RESERVED8)
TP_PCI643_B10: J2B2.B10
TP_PCI643_B14: J2B2.B14
TP_PCI643_B63: J2B2.B63
TP_PCI643_B92: J2B2.B92
TP_PCI643_B93: J2B2.B93
TP_SMBCLK_PCI_2: J3B2.A40
TP_SMBDATA_PCI_2: J3B2.A41

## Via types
v1: diameter 0.635, hole 0.356, TOP to BOTTOM, 43 vias

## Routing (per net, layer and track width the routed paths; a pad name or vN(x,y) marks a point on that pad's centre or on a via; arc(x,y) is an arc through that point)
GND: length 49.4
  TOP w0.127: 62.2,19.74 U3D1.P9 62.04,19.88 62.04,19.89 61.91,20.02 v1(61.62,20.32) 62.2,19.74 ; 68.77,31.32 68.9,31.45 v1(69.19,31.75) 68.61,31.17 U3D1.E14 68.77,31.31 68.77,31.32 ; v1(71.73,30.48) 71.15,29.9 U3D1.F16 71.31,30.04 71.31,30.05 71.44,30.18 v1(71.73,30.48) ; 53.15,30.05 53.15,30.04 U3D1.F2 53.31,29.9 v1(52.73,30.48) 53.02,30.18 53.15,30.05 ; v1(66.65,20.32) 66.36,20.02 66.23,19.89 66.23,19.88 U3D1.P12 66.07,19.74 v1(66.65,20.32) ; 63.69,17.34 63.69,17.35 63.82,17.48 v1(64.11,17.78) 63.53,17.2 U3D1.T10 63.69,17.34 ; 54.29,33.99 v1(54,34.29) 54.58,33.71 U3D1.C3 54.42,33.85 54.42,33.86 54.29,33.99 ; 51.88,36.39 51.88,36.4 51.75,36.53 v1(51.46,36.83) 52.04,36.25 U3D1.A1 51.88,36.39 ; 71.31,32.58 71.31,32.59 71.44,32.72 v1(71.73,33.02) 71.15,32.44 U3D1.D16 71.31,32.58 ; v1(67.92,17.78) 67.34,17.2 U3D1.T13 67.5,17.34 67.5,17.35 67.63,17.48 v1(67.92,17.78) ; 59.37,17.48 v1(59.08,17.78) 59.66,17.2 U3D1.T7 59.5,17.34 59.5,17.35 59.37,17.48 ; 66.36,31.45 v1(66.65,31.75) 66.07,31.17 U3D1.E12 66.23,31.31 66.23,31.32 66.36,31.45 ; 67.63,28.91 v1(67.92,29.21) 67.34,28.63 U3D1.G13 67.5,28.77 67.5,28.78 67.63,28.91 ; U3D1.P6 58.39,19.74 v1(57.81,20.32) 58.1,20.02 58.23,19.89 58.23,19.88 U3D1.P6 ; v1(67.92,30.48) 67.34,29.9 U3D1.F13 67.5,30.04 67.5,30.05 67.63,30.18 v1(67.92,30.48) ; 58.23,35.12 58.23,35.13 58.1,35.26 v1(57.81,35.56) 58.39,34.98 U3D1.B6 58.23,35.12 ; 62.04,35.13 62.04,35.12 U3D1.B9 62.2,34.98 v1(61.62,35.56) 61.91,35.26 62.04,35.13 ; 72.71,16.21 v1(73,16.51) 72.42,15.93 72.39,15.88 72.58,16.07 72.58,16.08 72.71,16.21 ; 67.5,21.15 U3D1.N13 67.34,21.01 v1(67.92,21.59) 67.63,21.29 67.5,21.16 67.5,21.15 ; U3D1.M16 71.31,22.42 71.31,22.43 71.44,22.56 v1(71.73,22.86) 71.15,22.28 U3D1.M16 ; v1(52.73,25.4) 53.02,25.1 53.15,24.97 53.15,24.96 U3D1.K2 53.31,24.82 v1(52.73,25.4) ; 56.96,23.7 56.83,23.83 v1(56.54,24.13) 57.12,23.55 U3D1.L5 56.96,23.69 56.96,23.7 ; 66.23,35.13 66.36,35.26 v1(66.65,35.56) 66.07,34.98 U3D1.B12 66.23,35.12 66.23,35.13 ; v1(70.46,19.05) 69.88,18.47 69.85,18.41 70.04,18.61 70.04,18.62 70.17,18.75 v1(70.46,19.05) ; 72.58,36.39 U3D1.A17 72.42,36.25 v1(73,36.83) 72.71,36.53 72.58,36.4 72.58,36.39 ; U3D1.P2 53.15,19.88 53.15,19.89 53.02,20.02 v1(52.73,20.32) 53.31,19.74 U3D1.P2 ; U3D1.F5 56.96,30.04 56.96,30.05 56.83,30.18 v1(56.54,30.48) 57.12,29.9 U3D1.F5 ; 71.44,18.75 71.31,18.62 71.31,18.61 71.12,18.41 71.15,18.47 v1(71.73,19.05) 71.44,18.75
+3_3V: length 22.9
  TOP w0.127: 55.56,30.18 v1(55.27,30.48) 55.85,29.9 U3D1.F4 55.69,30.04 55.69,30.05 55.56,30.18 ; 56.83,22.56 56.96,22.43 56.96,22.42 U3D1.M5 57.12,22.28 v1(56.54,22.86) 56.83,22.56 ; U3D1.E13 67.5,31.31 67.5,31.32 67.63,31.45 v1(67.92,31.75) 67.34,31.17 U3D1.E13 ; 72.42,27.36 U3D1.H17 72.58,27.5 72.58,27.51 72.71,27.64 v1(73,27.94) 72.42,27.36 ; 56.96,31.32 56.83,31.45 v1(56.54,31.75) 57.12,31.17 U3D1.E5 56.96,31.31 56.96,31.32 ; 67.5,23.69 67.5,23.7 67.63,23.83 v1(67.92,24.13) 67.34,23.55 U3D1.L13 67.5,23.69 ; v1(57.81,21.59) 58.39,21.01 U3D1.N6 58.23,21.15 58.23,21.16 58.1,21.29 v1(57.81,21.59) ; 68.77,30.05 68.9,30.18 v1(69.19,30.48) 68.61,29.9 U3D1.F14 68.77,30.04 68.77,30.05 ; v1(59.08,20.32) 59.66,19.74 U3D1.P7 59.5,19.88 59.5,19.89 59.37,20.02 v1(59.08,20.32) ; 56.83,26.37 v1(56.54,26.67) 57.12,26.09 U3D1.J5 56.96,26.23 56.96,26.24 56.83,26.37 ; 67.5,22.42 U3D1.M13 67.34,22.28 v1(67.92,22.86) 67.63,22.56 67.5,22.43 67.5,22.42 ; v1(66.65,21.59) 66.07,21.01 U3D1.N12 66.23,21.15 66.23,21.16 66.36,21.29 v1(66.65,21.59) ; v1(67.92,26.67) 67.34,26.09 U3D1.J13 67.5,26.23 67.5,26.24 67.63,26.37 v1(67.92,26.67)
AD0: length 38.8
  LAYER_6 w0.127: 95.25,64.77 81.29,64.77 80.38,63.87 79.64,63.87 78.73,64.77 57.15,64.77
AD1: length 50.5
  LAYER_8 w0.127: 52.07,64.77 55.87,64.77 56.78,63.87 57.52,63.87 58.43,64.77 73.65,64.77 74.56,63.87 75.3,63.87 76.21,64.77 93.97,64.77 94.88,63.87 95.62,63.87 96.53,64.77 100.33,64.77
AD2: length 33.8
  LAYER_8 w0.127: 92.71,66.04 78.75,66.04 77.84,65.14 77.1,65.14 76.19,66.04 59.69,66.04
AD3: length 50.5
  LAYER_8 w0.127: 52.07,67.31 55.87,67.31 56.78,66.41 57.52,66.41 58.43,67.31 73.65,67.31 74.56,66.41 75.3,66.41 76.21,67.31 93.97,67.31 94.88,66.41 95.62,66.41 96.53,67.31 100.33,67.31
AD4: length 33.8
  LAYER_6 w0.127: 92.71,68.58 78.75,68.58 77.84,67.68 77.1,67.68 76.19,68.58 59.69,68.58
AD5: length 45.4
  LAYER_8 w0.127: 54.61,68.58 58.41,68.58 59.32,67.68 60.06,67.68 60.97,68.58 71.11,68.58 72.02,67.68 72.76,67.68 73.67,68.58 91.43,68.58 92.34,67.68 93.08,67.68 93.99,68.58 97.79,68.58
AD6: length 38.8
  LAYER_8 w0.127: 95.25,69.85 81.29,69.85 80.38,68.95 79.64,68.95 78.73,69.85 57.15,69.85
AD7: length 45.4
  LAYER_8 w0.127: 54.61,71.12 58.41,71.12 59.32,70.22 60.06,70.22 60.97,71.12 71.11,71.12 72.02,70.22 72.76,70.22 73.67,71.12 91.43,71.12 92.34,70.22 93.08,70.22 93.99,71.12 97.79,71.12
AD8: length 50.5
  LAYER_8 w0.127: 100.33,72.39 96.53,72.39 95.62,71.49 94.88,71.49 93.97,72.39 76.21,72.39 75.3,71.49 74.56,71.49 73.65,72.39 58.43,72.39 57.52,71.49 56.78,71.49 55.87,72.39 52.07,72.39
AD9: length 33.8
  LAYER_8 w0.127: 92.71,76.2 78.75,76.2 77.84,77.1 77.1,77.1 76.19,76.2 59.69,76.2
AD10: length 50.5
  LAYER_8 w0.127: 52.07,77.47 55.87,77.47 56.78,76.57 57.52,76.57 58.43,77.47 73.65,77.47 74.56,76.57 75.3,76.57 76.21,77.47 93.97,77.47 94.88,76.57 95.62,76.57 96.53,77.47 100.33,77.47
AD11: length 33.8
  LAYER_6 w0.127: 92.71,78.74 78.75,78.74 77.84,77.84 77.1,77.84 76.19,78.74 59.69,78.74
AD12: length 45.4
  LAYER_8 w0.127: 97.79,78.74 93.99,78.74 93.08,77.84 92.34,77.84 91.43,78.74 73.67,78.74 72.76,77.84 72.02,77.84 71.11,78.74 60.97,78.74 60.06,77.84 59.32,77.84 58.41,78.74 54.61,78.74
AD13: length 38.8
  LAYER_8 w0.127: 95.25,80.01 81.29,80.01 80.38,79.11 79.64,79.11 78.73,80.01 57.15,80.01
AD14: length 45.4
  LAYER_8 w0.127: 97.79,81.28 93.99,81.28 93.08,80.38 92.34,80.38 91.43,81.28 73.67,81.28 72.76,80.38 72.02,80.38 71.11,81.28 60.97,81.28 60.06,80.38 59.32,80.38 58.41,81.28 54.61,81.28
AD15: length 38.8
  LAYER_6 w0.127: 57.15,82.55 78.73,82.55 79.64,81.65 80.38,81.65 81.29,82.55 95.25,82.55
AD16: length 38.9
  LAYER_6 w0.127: 57.15,97.79 57.25,97.69 74.83,97.69 74.93,97.79 78.73,97.79 79.64,96.89 80.38,96.89 81.29,97.79 95.25,97.79
AD17: length 58.6
  TOP w0.127: 52.07,97.79 55.87,97.79 56.78,96.89 57.52,96.89 58.43,97.79 73.65,97.79 74.56,96.89 75.3,96.89 76.21,97.79 93.97,97.79 94.88,96.89 95.62,96.89 96.53,97.79 102.92,97.79 104.32,96.39 107.62,96.39 107.77,96.55
AD18: length 33.8
  TOP w0.127: 59.69,99.06 76.19,99.06 77.1,98.16 77.84,98.16 78.75,99.06 92.71,99.06
AD19: length 50.5
  TOP w0.127: 52.07,100.33 55.87,100.33 56.78,99.43 57.52,99.43 58.43,100.33 73.65,100.33 74.56,99.43 75.3,99.43 76.21,100.33 93.97,100.33 94.88,99.43 95.62,99.43 96.53,100.33 100.33,100.33
AD20: length 33.8
  LAYER_6 w0.127: 59.69,101.6 76.19,101.6 77.1,100.7 77.84,100.7 78.75,101.6 92.71,101.6
AD21: length 56.4
  TOP w0.127: 107.77,99.31 104.88,99.31 102.54,101.65 97.84,101.65 97.79,101.6 93.99,101.6 93.08,100.7 92.34,100.7 91.43,101.6 73.67,101.6 72.76,100.7 72.02,100.7 71.11,101.6 60.97,101.6 60.06,100.7 59.32,100.7 58.41,101.6 54.61,101.6
AD22: length 38.8
  TOP w0.127: 57.15,102.87 78.73,102.87 79.64,101.97 80.38,101.97 81.29,102.87 95.25,102.87
AD23: length 56.3
  TOP w0.127: 54.61,104.14 58.41,104.14 59.32,103.24 60.06,103.24 60.97,104.14 71.11,104.14 72.02,103.24 72.76,103.24 73.67,104.14 91.43,104.14 92.34,103.24 93.08,103.24 93.99,104.14 105.71,104.14 107.77,102.08
AD24: length 33.8
  TOP w0.127: 59.69,106.68 76.19,106.68 77.1,105.78 77.84,105.78 78.75,106.68 92.71,106.68
AD25: length 58.1
  TOP w0.127: 52.07,107.95 55.87,107.95 56.78,107.05 57.52,107.05 58.43,107.95 73.65,107.95 74.56,107.05 75.3,107.05 76.21,107.95 93.97,107.95 94.88,107.05 95.62,107.05 96.53,107.95 107.44,107.95 107.77,107.62
AD26: length 33.8
  LAYER_3 w0.127: 59.69,109.22 76.19,109.22 77.1,110.12 77.84,110.12 78.75,109.22 92.71,109.22
AD27: length 55.9
  TOP w0.127: 54.61,109.22 58.41,109.22 59.32,108.32 60.06,108.32 60.97,109.22 71.11,109.22 72.02,108.32 72.76,108.32 73.67,109.22 91.43,109.22 92.34,108.32 93.08,108.32 93.99,109.22 106.6,109.22 107.77,110.39
AD28: length 38.8
  BOTTOM w0.127: 95.25,110.49 81.29,110.49 80.38,109.59 79.64,109.59 78.73,110.49 57.15,110.49
AD29: length 56
  TOP w0.127: 107.77,113.16 106.38,111.76 97.79,111.76
  LAYER_8 w0.127: 97.79,111.76 93.99,111.76 93.08,110.86 92.34,110.86 91.43,111.76 73.67,111.76 72.76,110.86 72.02,110.86 71.11,111.76 60.97,111.76 60.06,110.86 59.32,110.86 58.41,111.76 54.61,111.76
AD30: length 38.8
  LAYER_3 w0.127: 95.25,113.03 81.29,113.03 80.38,112.13 79.64,112.13 78.73,113.03 57.15,113.03
AD31: length 59.1
  TOP w0.127: 52.07,113.03 55.87,113.03 56.78,112.13 57.52,112.13 58.43,113.03 73.65,113.03 74.56,112.13 75.3,112.13 76.21,113.03 93.97,113.03 94.88,112.13 95.62,112.13 96.53,113.03 104.88,113.03 107.77,115.93
C_BE_L0: length 38.8
  LAYER_6 w0.127: 95.25,72.39 81.29,72.39 80.38,71.49 79.64,71.49 78.73,72.39 57.15,72.39
C_BE_L1: length 50.5
  LAYER_8 w0.127: 52.07,82.55 55.87,82.55 56.78,81.65 57.52,81.65 58.43,82.55 73.65,82.55 74.56,81.65 75.3,81.65 76.21,82.55 93.97,82.55 94.88,81.65 95.62,81.65 96.53,82.55 100.33,82.55
C_BE_L2: length 56.6
  TOP w0.127: 54.61,96.52 58.41,96.52 59.32,95.62 60.06,95.62 60.97,96.52 71.11,96.52 72.02,95.62 72.76,95.62 73.67,96.52 91.43,96.52 92.34,95.62 93.08,95.62 93.99,96.52 97.79,96.52 98.22,96.09 99.89,96.09 99.96,96.15 102.65,96.15 105.03,93.78 107.77,93.78
C_BE_L3: length 58.2
  TOP w0.127: 107.77,104.85 107.21,105.41 96.53,105.41 95.62,104.51 94.88,104.51 93.97,105.41 76.21,105.41 75.3,104.51 74.56,104.51 73.65,105.41 58.43,105.41 57.52,104.51 56.78,104.51 55.87,105.41 52.07,105.41
DEVSEL_L: length 56.7
  TOP w0.127: 54.61,91.44 58.41,91.44 59.32,90.54 60.06,90.54 60.97,91.44 71.11,91.44 72.02,90.54 72.76,90.54 73.67,91.44 91.43,91.44 92.34,90.54 93.08,90.54 93.99,91.44 97.79,91.44
  LAYER_6 w0.127: 97.79,91.44 104.57,91.44 107.77,88.24
FRAME_L: length 38.8
  TOP w0.127: 57.15,95.25 78.73,95.25 79.64,94.35 80.38,94.35 81.29,95.25 95.25,95.25
HL_B0: length 1.8
  TOP w0.127: 60.77,17.35 60.77,17.34 U3D1.T8 60.93,17.2 60.35,17.78 60.64,17.48 60.77,17.35
HL_B1: length 1.8
  TOP w0.127: 60.93,15.93 60.96,15.88 60.77,16.07 60.77,16.08 60.64,16.21 60.35,16.51 60.93,15.93
HL_B2: length 1.8
  TOP w0.127: 62.04,18.62 62.04,18.61 62.23,18.41 62.2,18.47 61.62,19.05 61.91,18.75 62.04,18.62
HL_B3: length 1.8
  TOP w0.127: 62.04,17.35 62.04,17.34 U3D1.T9 62.2,17.2 61.62,17.78 61.91,17.48 62.04,17.35
HL_B4: length 1.8
  TOP w0.127: 64.11,16.51 63.82,16.21 63.69,16.08 63.69,16.07 63.5,15.88 63.53,15.93 64.11,16.51
HL_B5: length 1.8
  TOP w0.127: U3D1.P11 64.8,19.74 65.38,20.32 65.09,20.02 64.96,19.89 64.96,19.88 U3D1.P11
HL_B6: length 1.8
  TOP w0.127: 65.09,18.75 65.38,19.05 64.8,18.47 64.77,18.41 64.96,18.61 64.96,18.62 65.09,18.75
HL_B7: length 1.8
  TOP w0.127: 64.8,17.2 65.38,17.78 65.09,17.48 64.96,17.35 64.96,17.34 U3D1.T11 64.8,17.2
HL_B8: length 1.8
  TOP w0.127: 67.92,20.32 67.63,20.02 67.5,19.89 67.5,19.88 U3D1.P13 67.34,19.74 67.92,20.32
HL_B9: length 1.8
  TOP w0.127: 67.5,18.62 67.63,18.75 67.92,19.05 67.34,18.47 67.31,18.41 67.5,18.61 67.5,18.62
HL_B10: length 1.8
  TOP w0.127: 67.5,16.07 67.5,16.08 67.63,16.21 67.92,16.51 67.34,15.93 67.31,15.88 67.5,16.07
HL_B12: length 1.8
  TOP w0.127: 68.9,16.21 69.19,16.51 68.61,15.93 68.58,15.88 68.77,16.07 68.77,16.08 68.9,16.21
HL_B13: length 1.8
  TOP w0.127: U3D1.T15 70.04,17.34 70.04,17.35 70.17,17.48 70.46,17.78 69.88,17.2 U3D1.T15
HL_B14: length 1.8
  TOP w0.127: 69.88,15.93 69.85,15.88 70.04,16.07 70.04,16.08 70.17,16.21 70.46,16.51 69.88,15.93
HL_B15: length 1.8
  TOP w0.127: 71.31,16.07 71.31,16.08 71.44,16.21 71.73,16.51 71.15,15.93 71.12,15.88 71.31,16.07
HL_B17: length 1.8
  TOP w0.127: 66.04,18.41 66.07,18.47 66.65,19.05 66.36,18.75 66.23,18.62 66.23,18.61 66.04,18.41
HL_B18: length 1.8
  TOP w0.127: 65.09,16.21 65.38,16.51 64.8,15.93 64.77,15.88 64.96,16.07 64.96,16.08 65.09,16.21
HL_B19: length 1.8
  TOP w0.127: 66.23,17.35 66.36,17.48 66.65,17.78 66.07,17.2 U3D1.T12 66.23,17.34 66.23,17.35
HLB_STB0: length 1.8
  TOP w0.127: 63.5,18.41 63.53,18.47 64.11,19.05 63.82,18.75 63.69,18.62 63.69,18.61 63.5,18.41
HLB_STB0_L: length 1.8
  TOP w0.127: 62.04,16.07 62.23,15.88 62.2,15.93 61.62,16.51 61.91,16.21 62.04,16.08 62.04,16.07
HLB_STB1: length 1.8
  TOP w0.127: 68.77,17.34 U3D1.T14 68.61,17.2 69.19,17.78 68.9,17.48 68.77,17.35 68.77,17.34
HLB_STB1_L: length 1.8
  TOP w0.127: 68.61,18.47 69.19,19.05 68.9,18.75 68.77,18.62 68.77,18.61 68.58,18.41 68.61,18.47
HLB_VREF_P64H: length 1.8
  TOP w0.127: U3D1.T16 71.15,17.2 71.73,17.78 71.44,17.48 71.31,17.35 71.31,17.34 U3D1.T16
HLB_ZCOM_FROM_P64H: length 1.8
  TOP w0.127: 72.71,17.48 73,17.78 72.42,17.2 U3D1.T17 72.58,17.34 72.58,17.35 72.71,17.48
IRDY_L: length 56.6
  TOP w0.127: 54.61,93.98 58.41,93.98 59.32,93.08 60.06,93.08 60.97,93.98 71.11,93.98 72.02,93.08 72.76,93.08 73.67,93.98 91.43,93.98 92.34,93.08 93.08,93.08 93.99,93.98 97.79,93.98
  LAYER_6 w0.127: 107.77,91.01 104.8,93.98 97.79,93.98
P1_8V: length 3.5
  TOP w0.127: 63.69,19.88 63.69,19.89 63.82,20.02 v1(64.11,20.32) 63.53,19.74 U3D1.P10 63.69,19.88 ; 60.64,20.02 60.77,19.89 60.77,19.88 U3D1.P8 60.93,19.74 v1(60.35,20.32) 60.64,20.02
P64H_66MHZ_CLK: length 1.8
  TOP w0.127: 73,19.05 72.42,18.47 72.39,18.41 72.58,18.61 72.58,18.62 72.71,18.75 73,19.05
P64H_APICCLK_PD: length 1.8
  TOP w0.127: 72.42,24.82 U3D1.K17 72.58,24.96 72.58,24.97 72.71,25.1 73,25.4 72.42,24.82
P64H_APICD0_PD: length 1.8
  TOP w0.127: U3D1.G16 71.31,28.77 71.31,28.78 71.44,28.91 71.73,29.21 71.15,28.63 U3D1.G16
P64H_APICD1_PD: length 1.8
  TOP w0.127: 70.04,28.77 70.04,28.78 70.17,28.91 70.46,29.21 69.88,28.63 U3D1.G15 70.04,28.77
P66_ACK64_L: length 22.9
  TOP w0.127: 11.43,62.23 15.16,62.23 16.12,61.28 16.9,61.28 17.86,62.23 31.75,62.23 ; 51.88,30.04 U3D1.F1 52.04,29.9 51.46,30.48 51.75,30.18 51.88,30.05 51.88,30.04
P66_AD0: length 22.9
  TOP w0.127: U3D1.D1 52.04,32.44 51.46,33.02 51.75,32.72 51.88,32.59 51.88,32.58 U3D1.D1
  LAYER_8 w0.127: 16.51,64.77 30.4,64.77 31.36,63.82 32.14,63.82 33.1,64.77 36.83,64.77
P66_AD1: length 22.9
  TOP w0.127: 31.75,64.77 17.86,64.77 16.9,63.82 16.12,63.82 15.16,64.77 11.43,64.77 ; 51.88,33.85 U3D1.C1 52.04,33.71 51.46,34.29 51.75,33.99 51.88,33.86 51.88,33.85
P66_AD2: length 22.9
  TOP w0.127: 19.05,66.04 32.94,66.04 33.9,65.09 34.68,65.09 35.64,66.04 39.37,66.04 ; 52.04,34.98 51.46,35.56 51.75,35.26 51.88,35.13 51.88,35.12 U3D1.B1 52.04,34.98
